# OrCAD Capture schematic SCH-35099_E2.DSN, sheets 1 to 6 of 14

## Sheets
1 07 DMIC: size C; title: X-MIMXRT685-EVK; rev: E2; company: NXP Semiconductors; note: SCH-35099 PDF: SPF-35099; note: 6501 William Cannon Drive West; note: Austin, TX 78735-8598
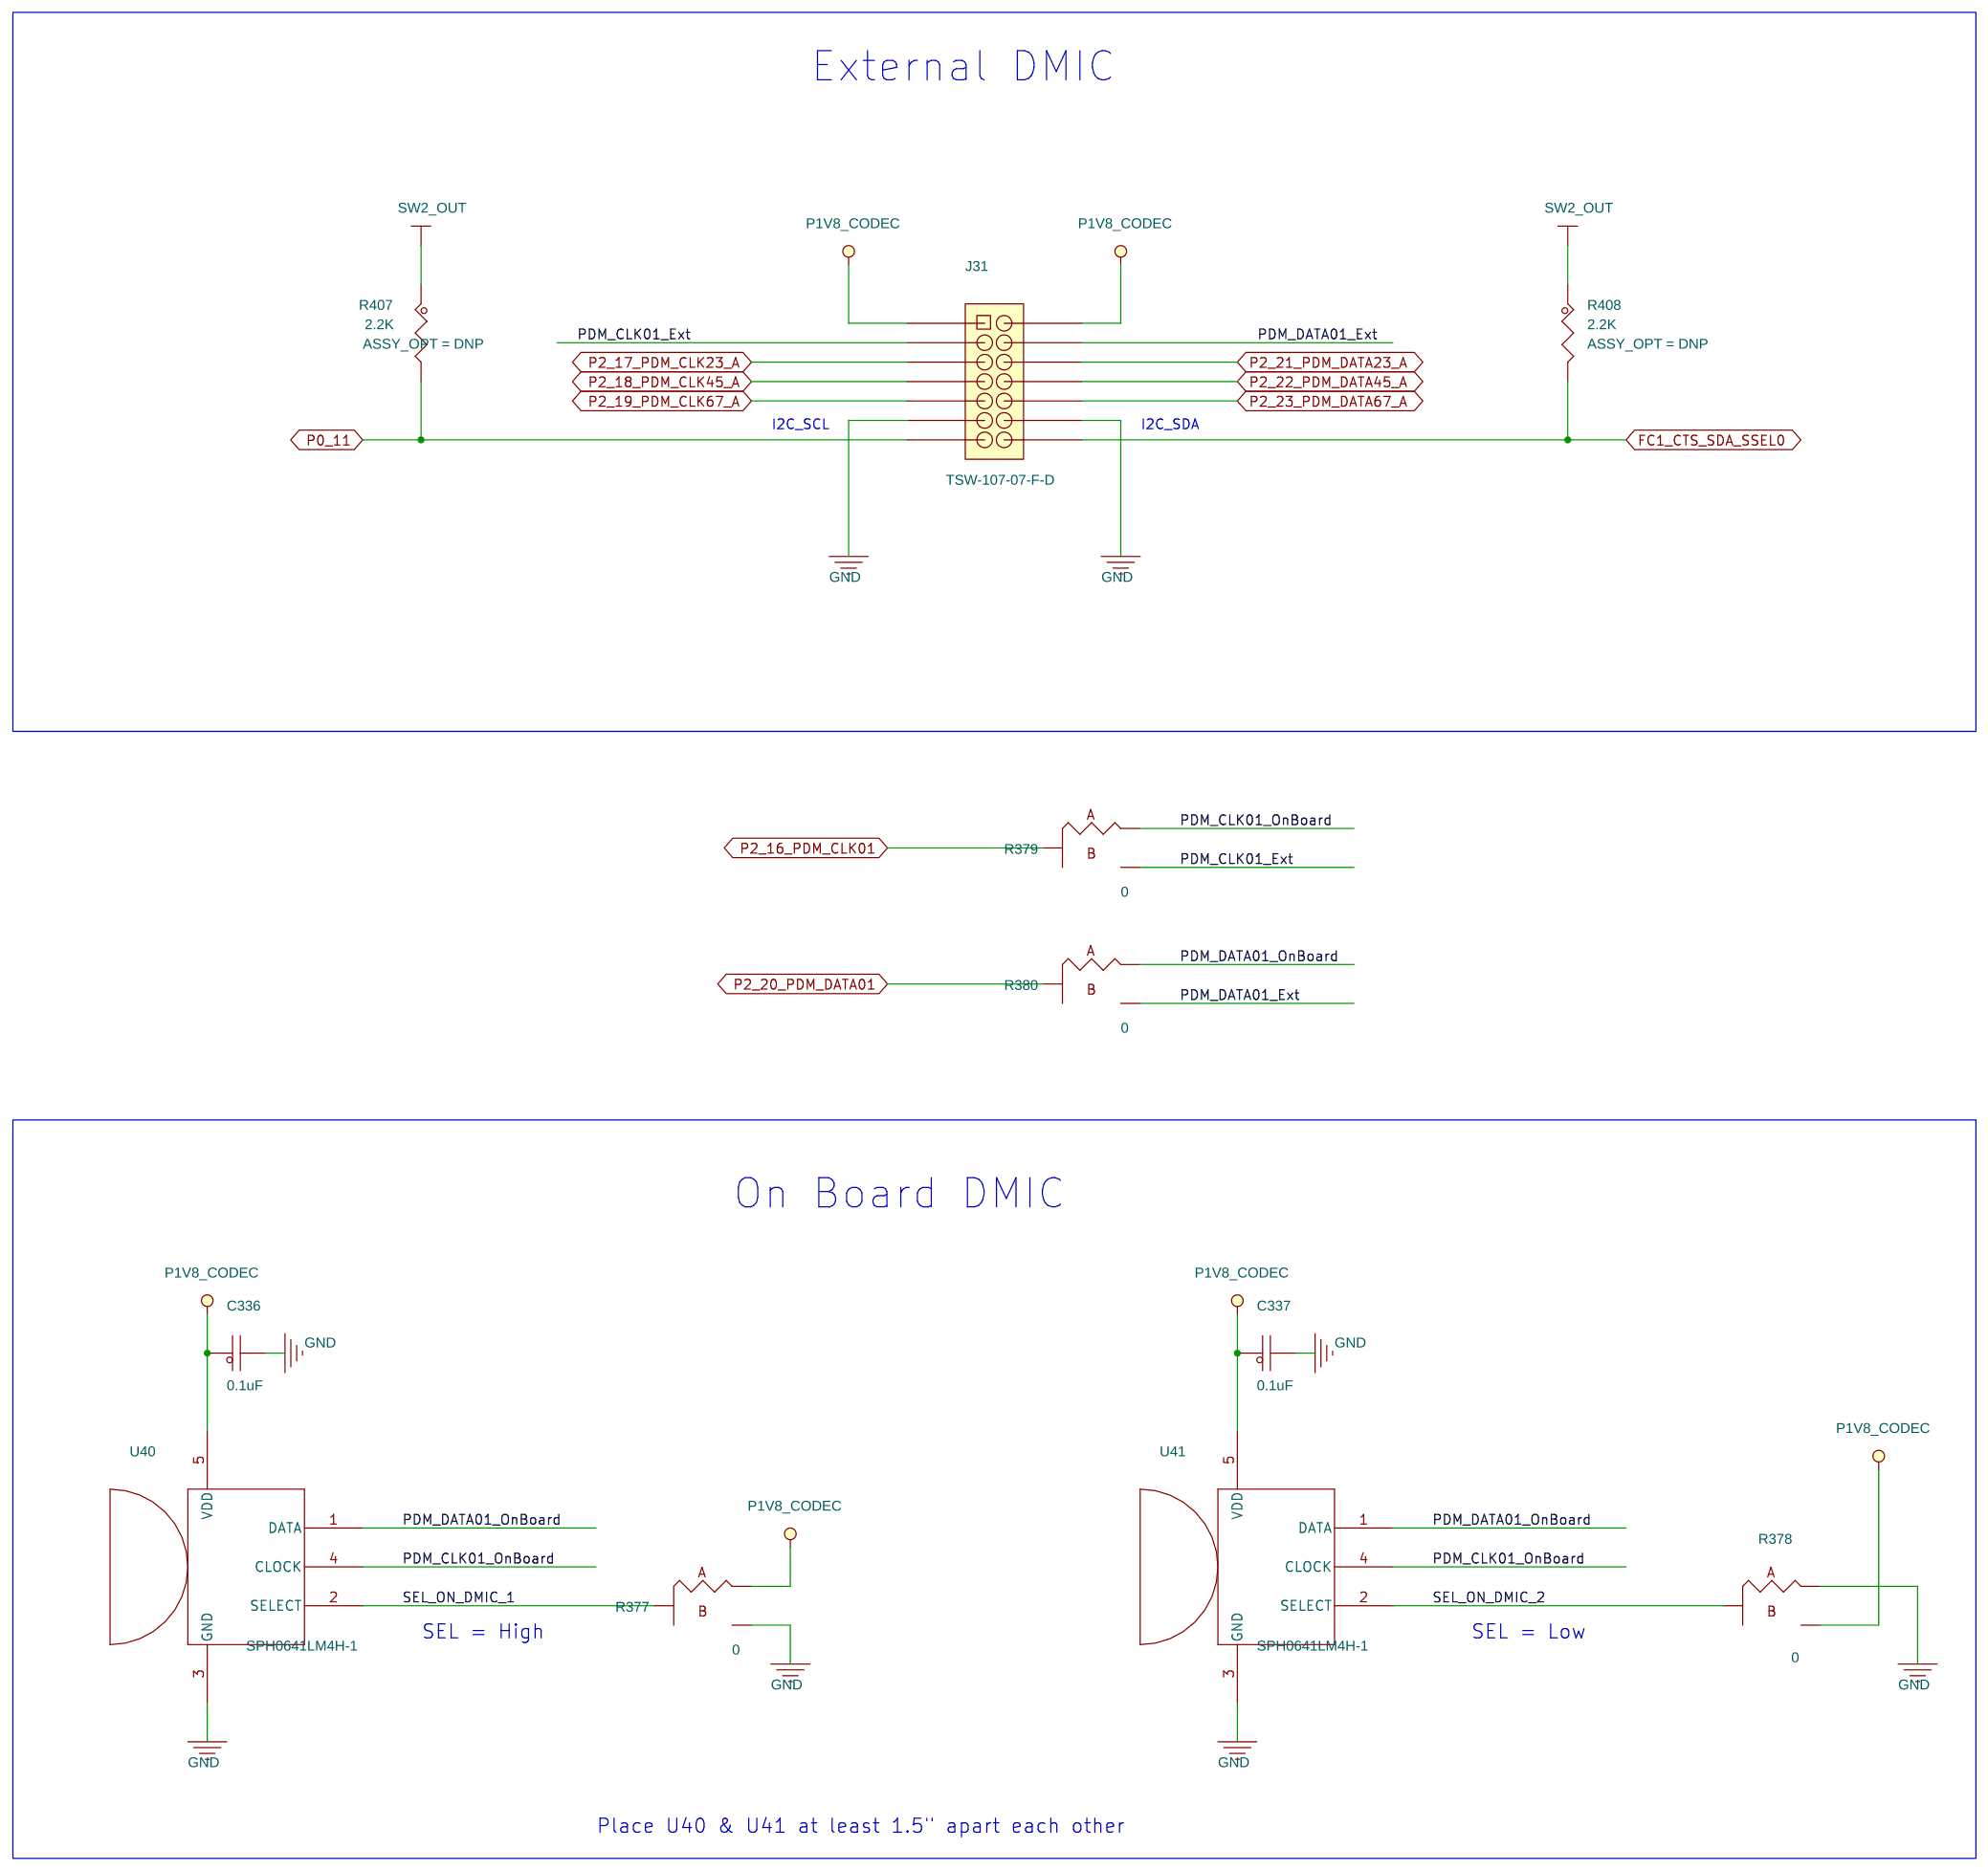
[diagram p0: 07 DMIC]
2 02 USB Supply Interface: size C
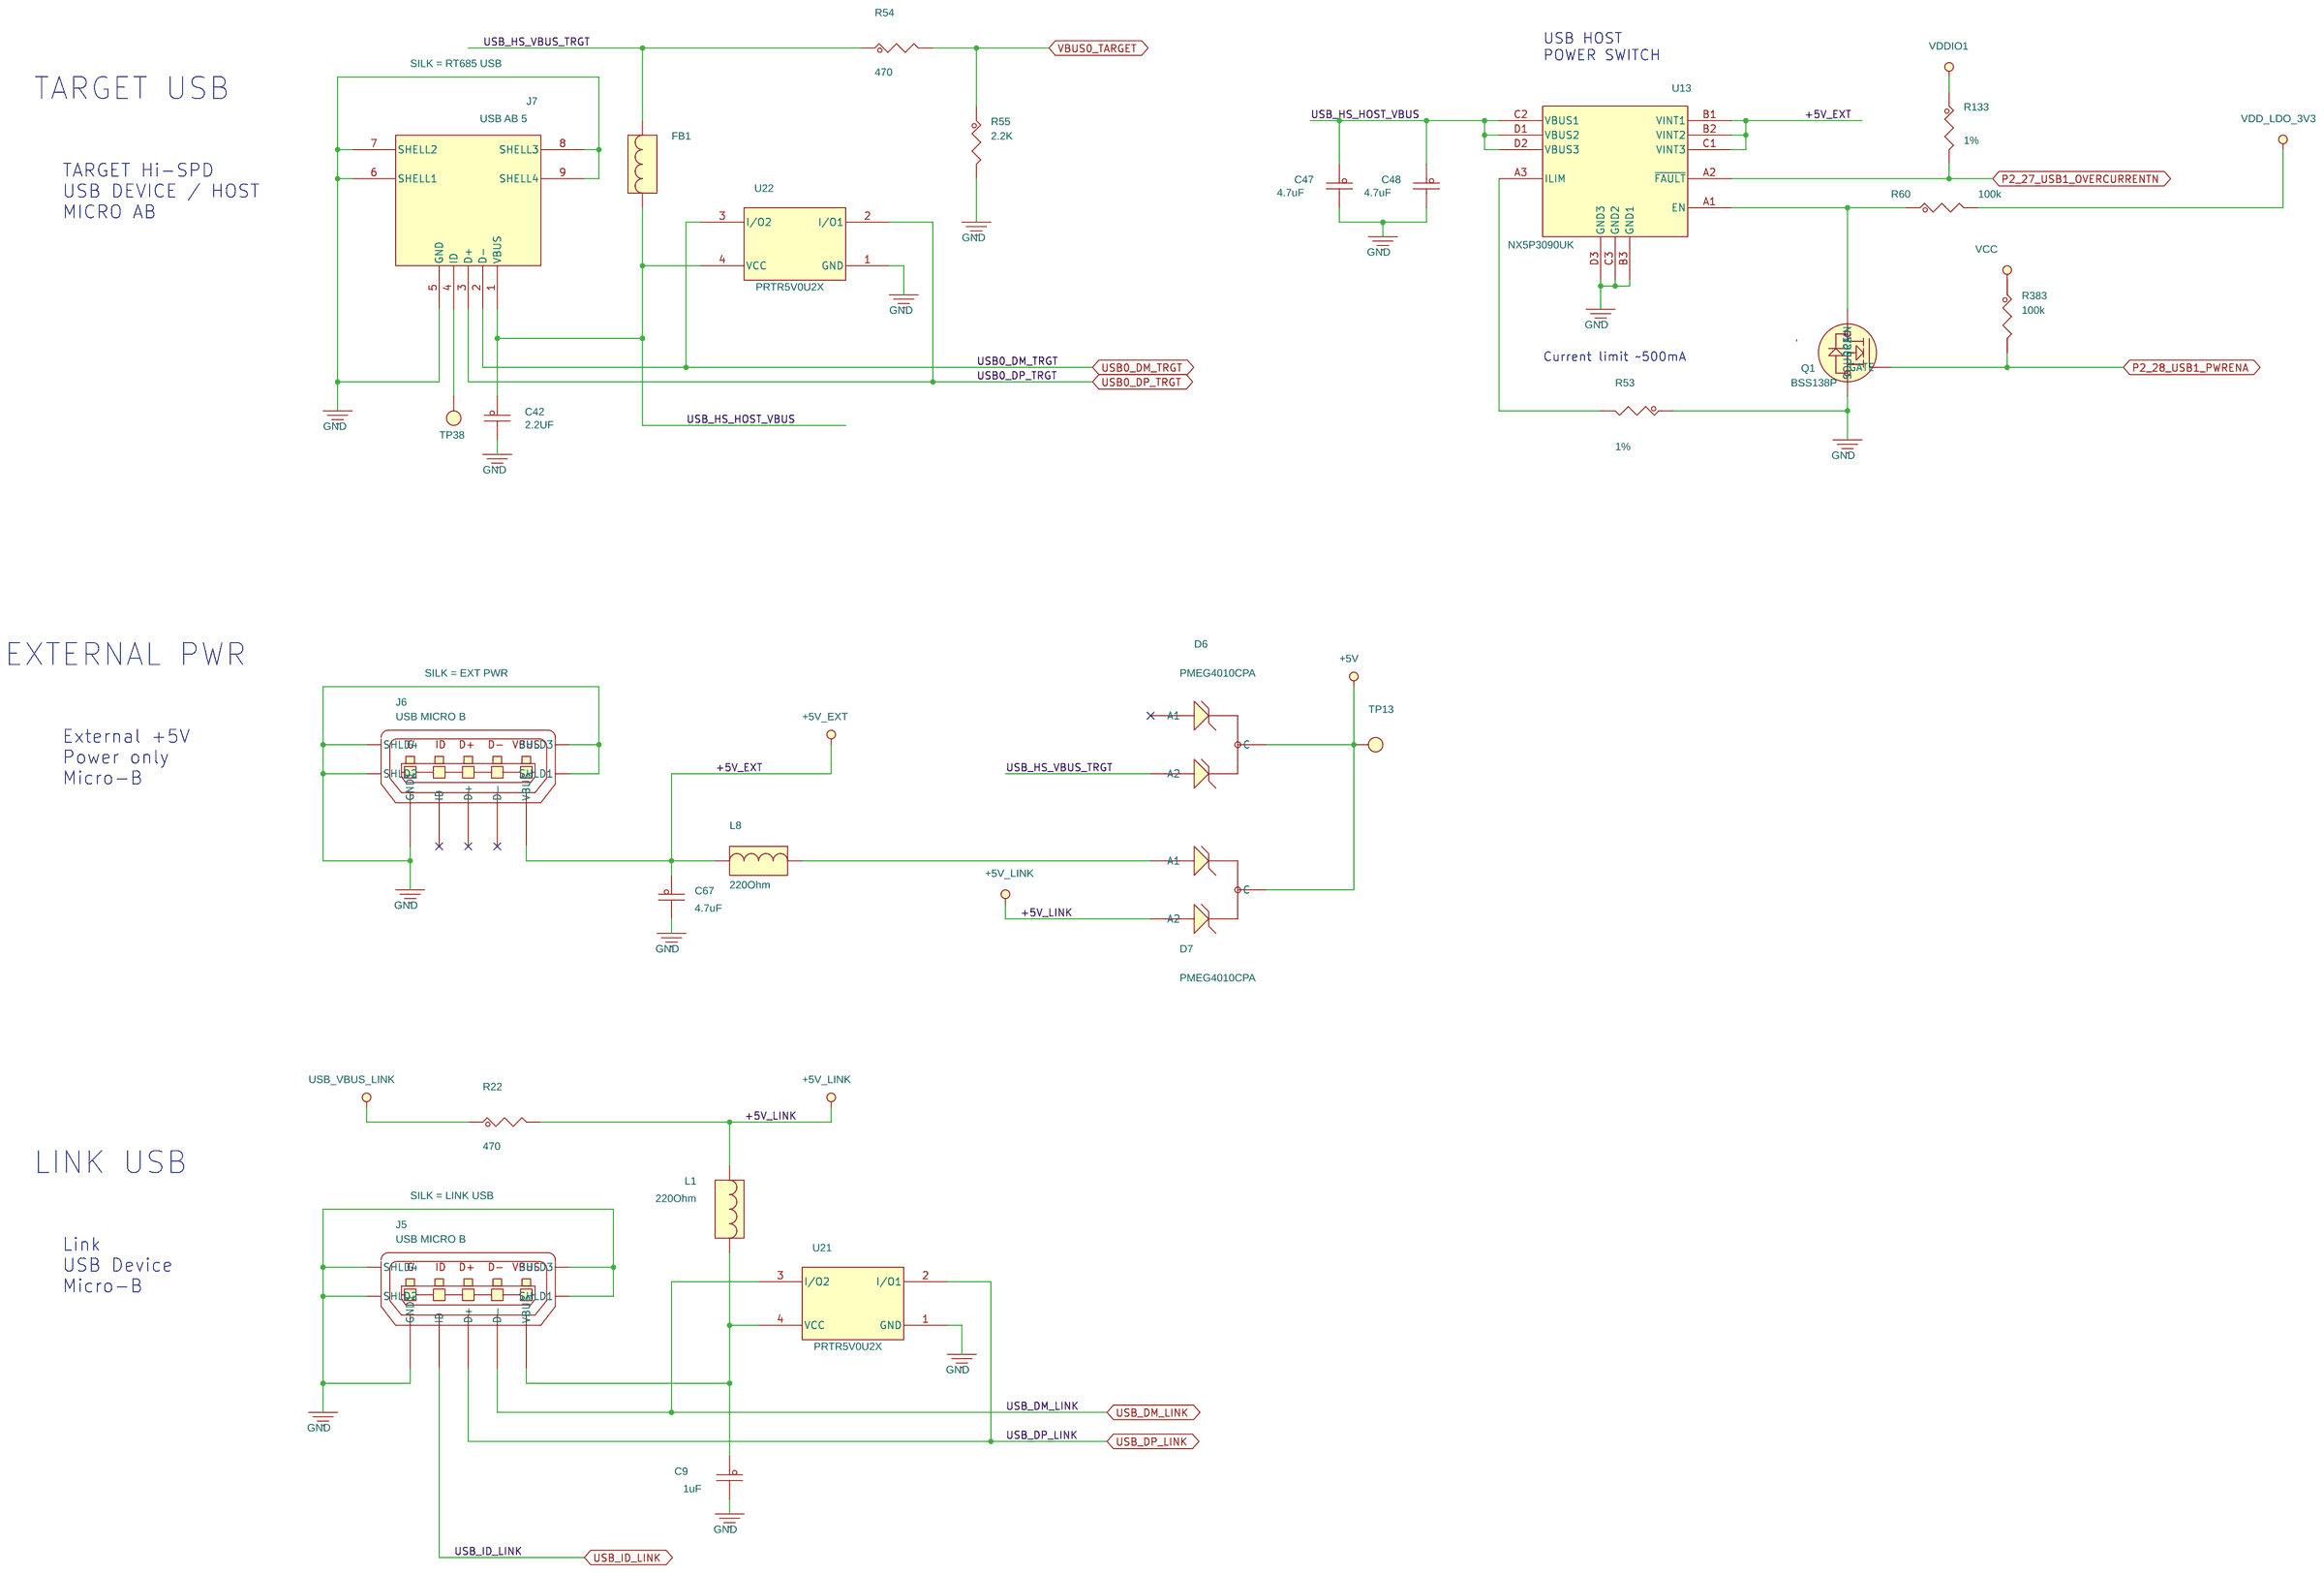
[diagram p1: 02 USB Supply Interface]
3 11 SD & M2 mini card: size C
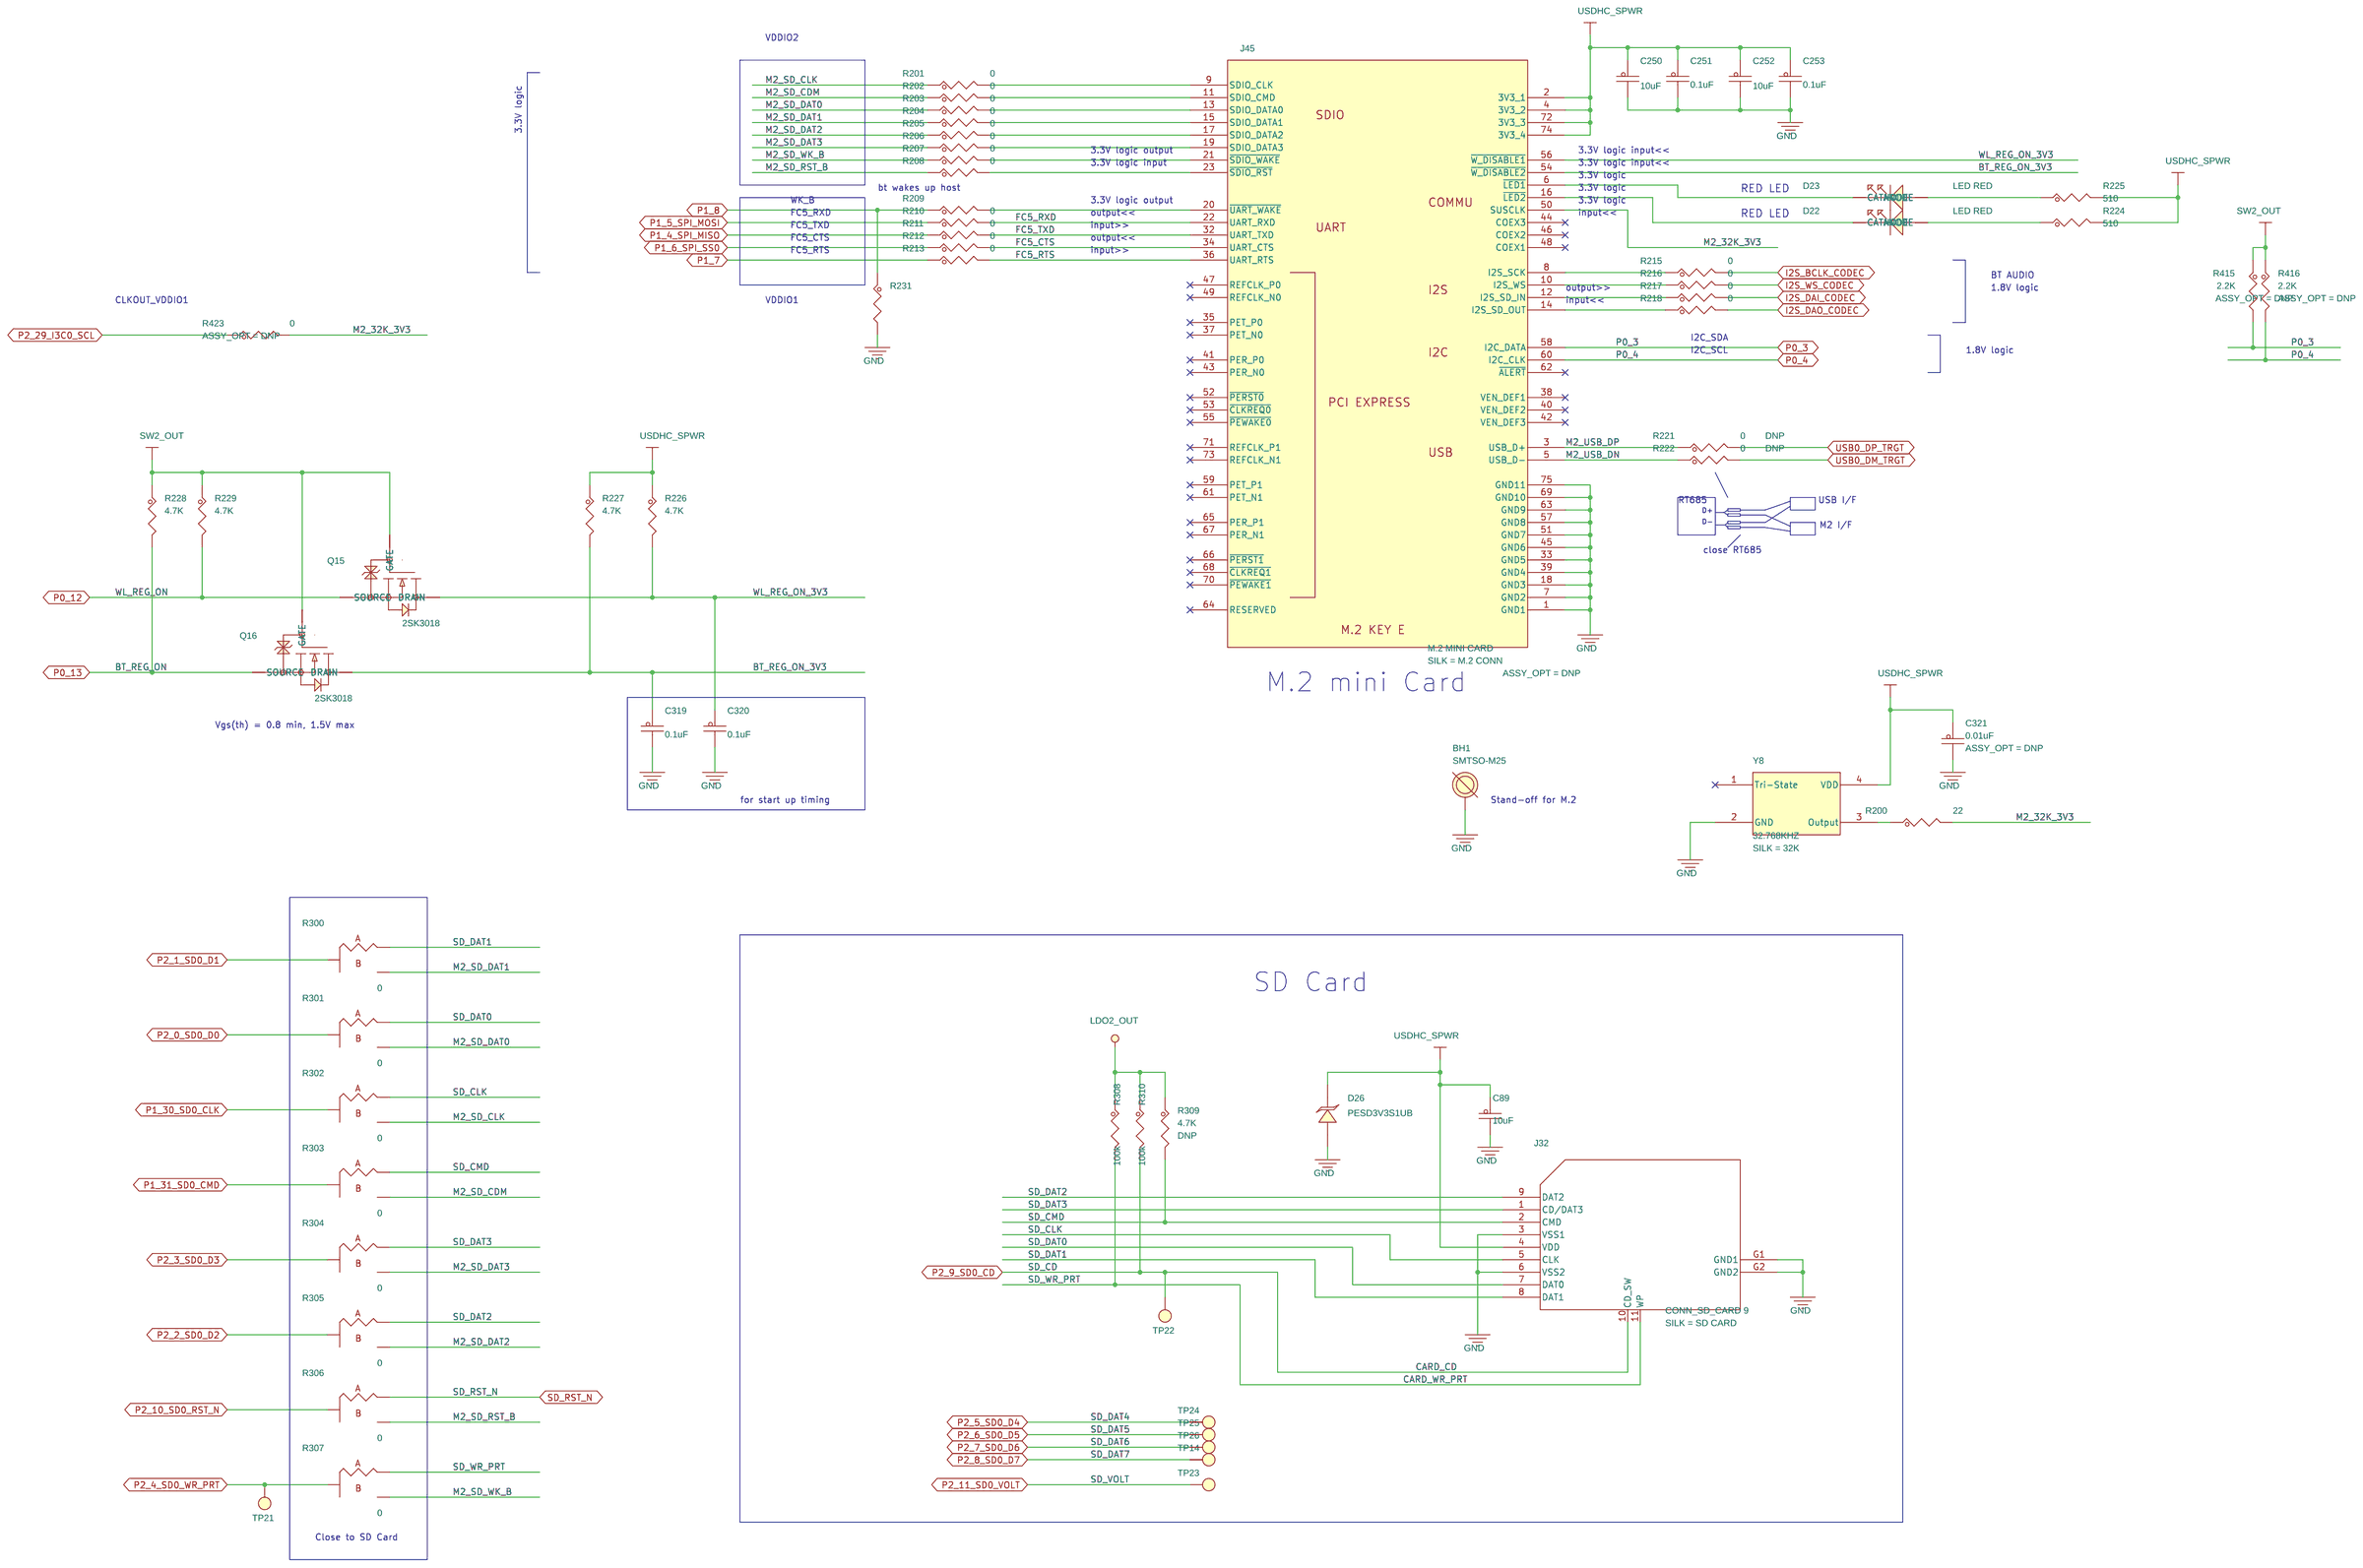
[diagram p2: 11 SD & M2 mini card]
4 12 System Reset: size C
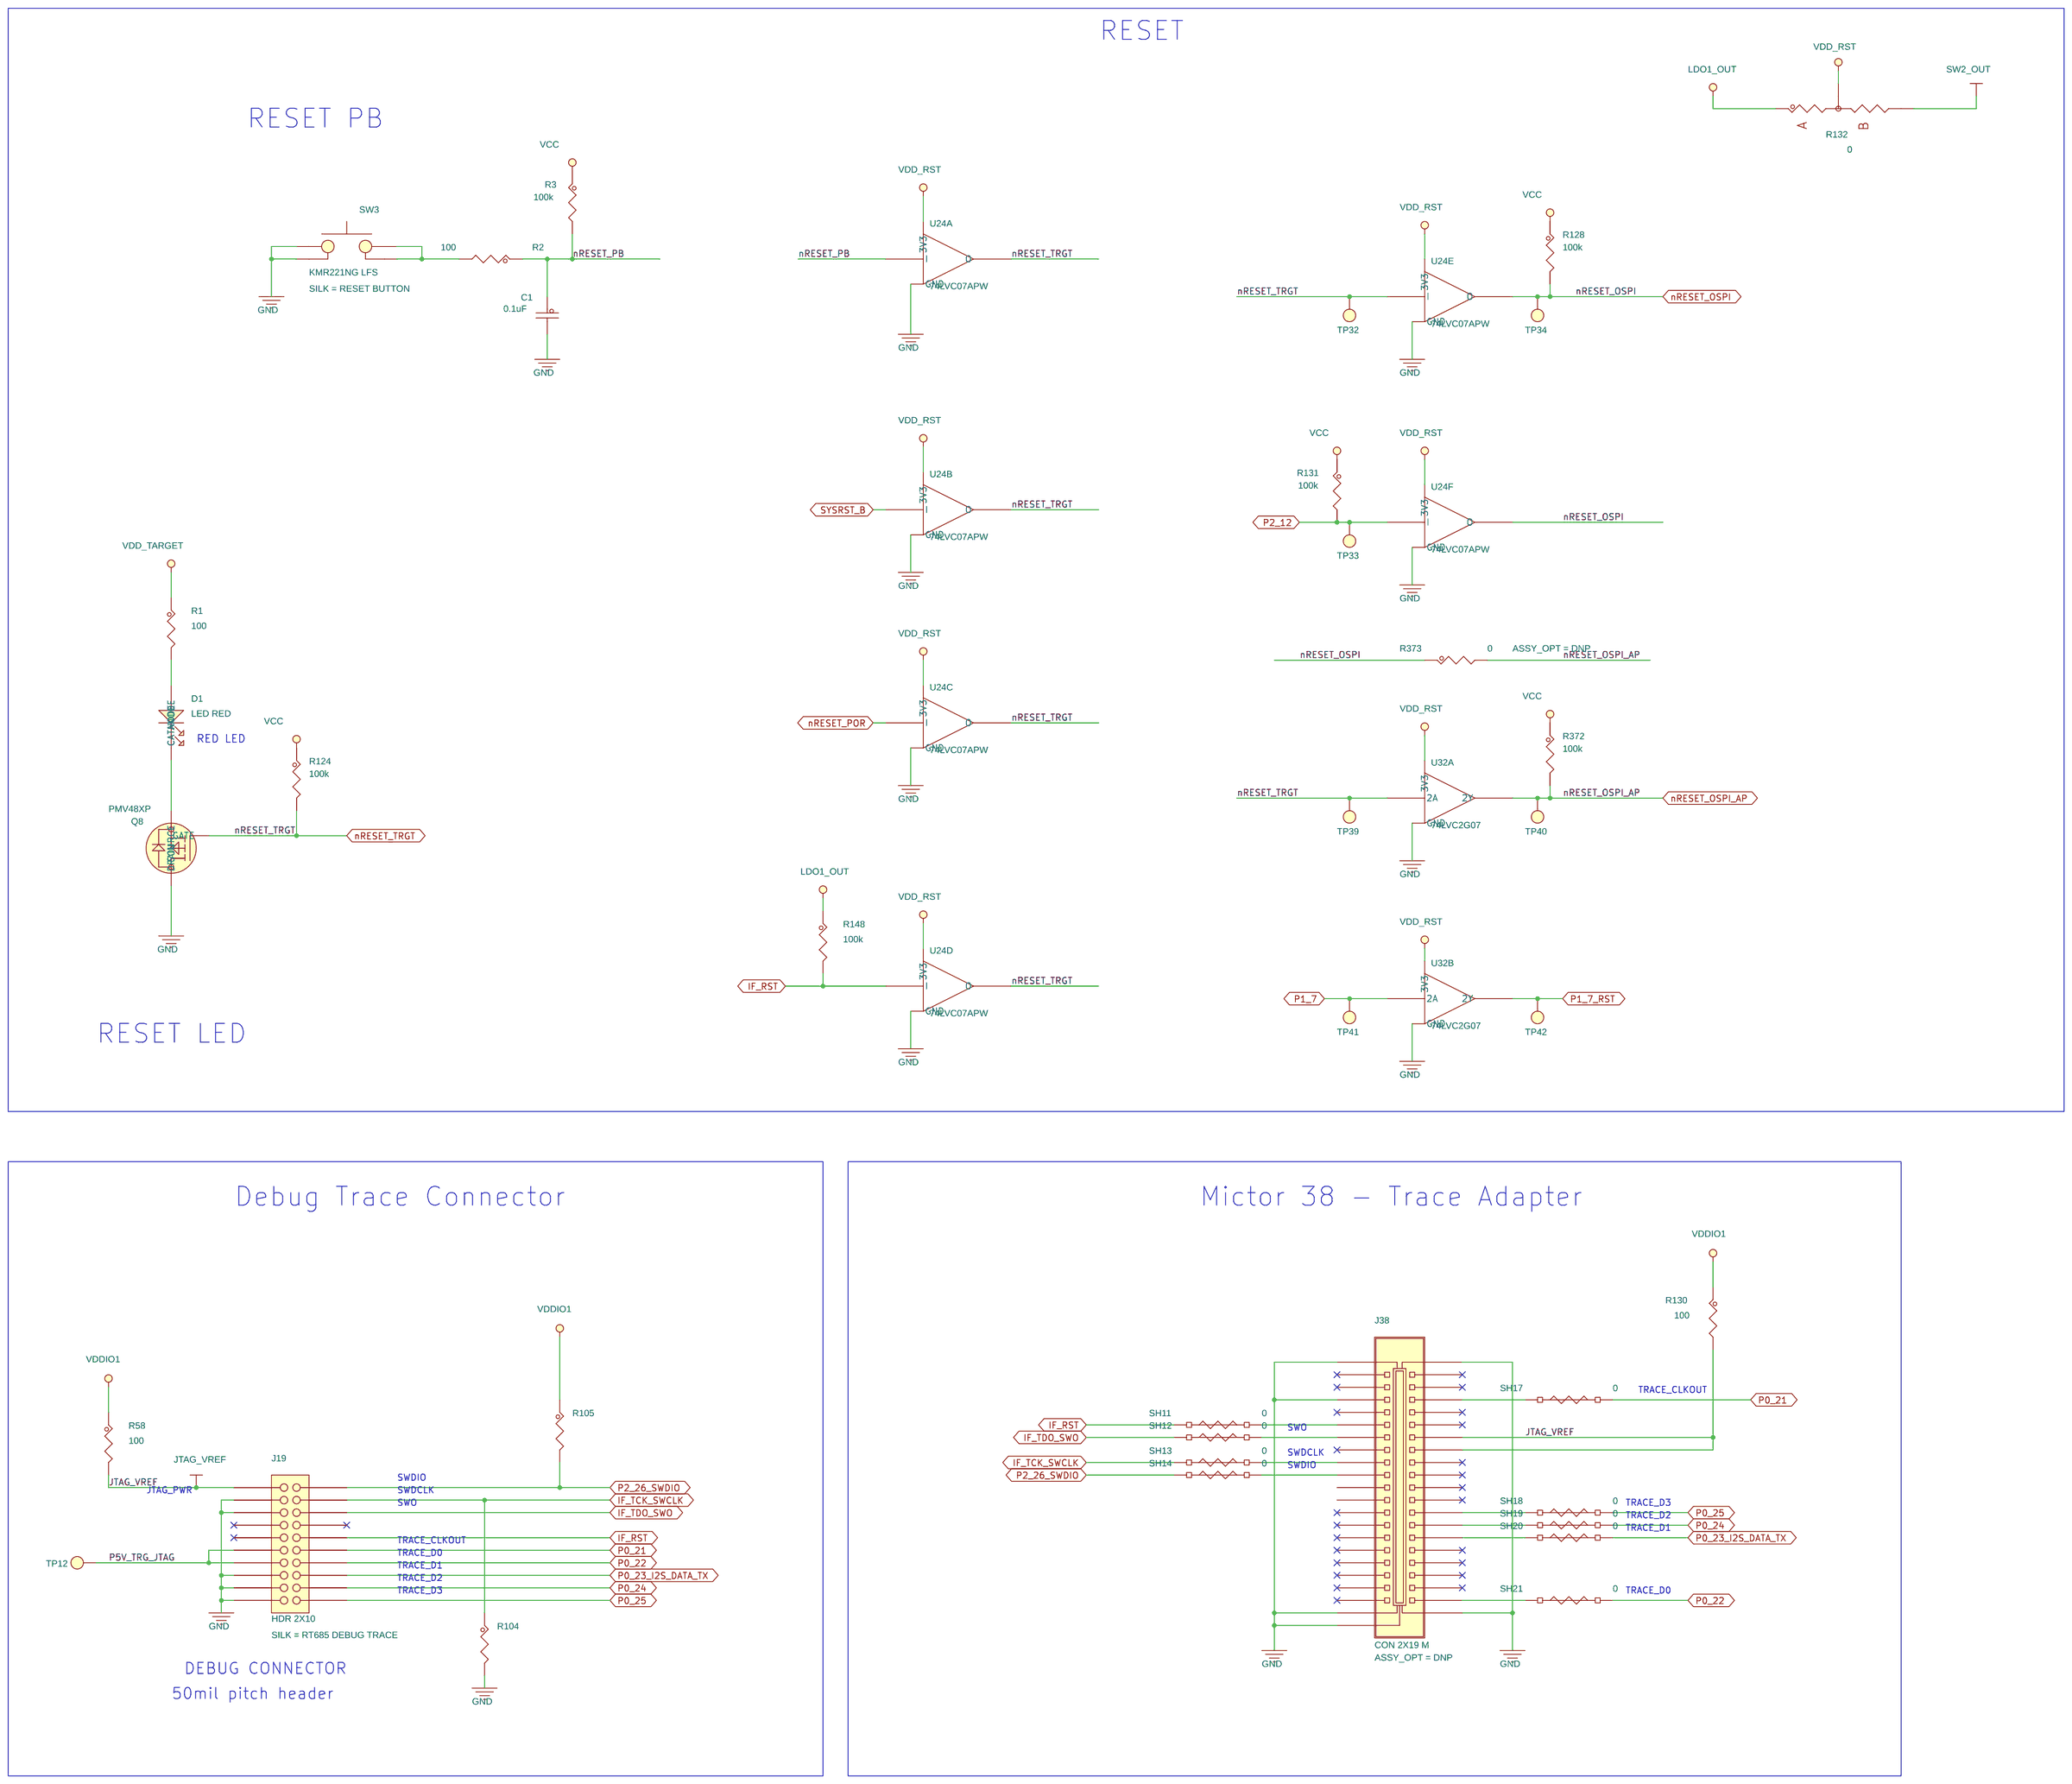
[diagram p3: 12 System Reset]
5 08 Audio Amp: size C
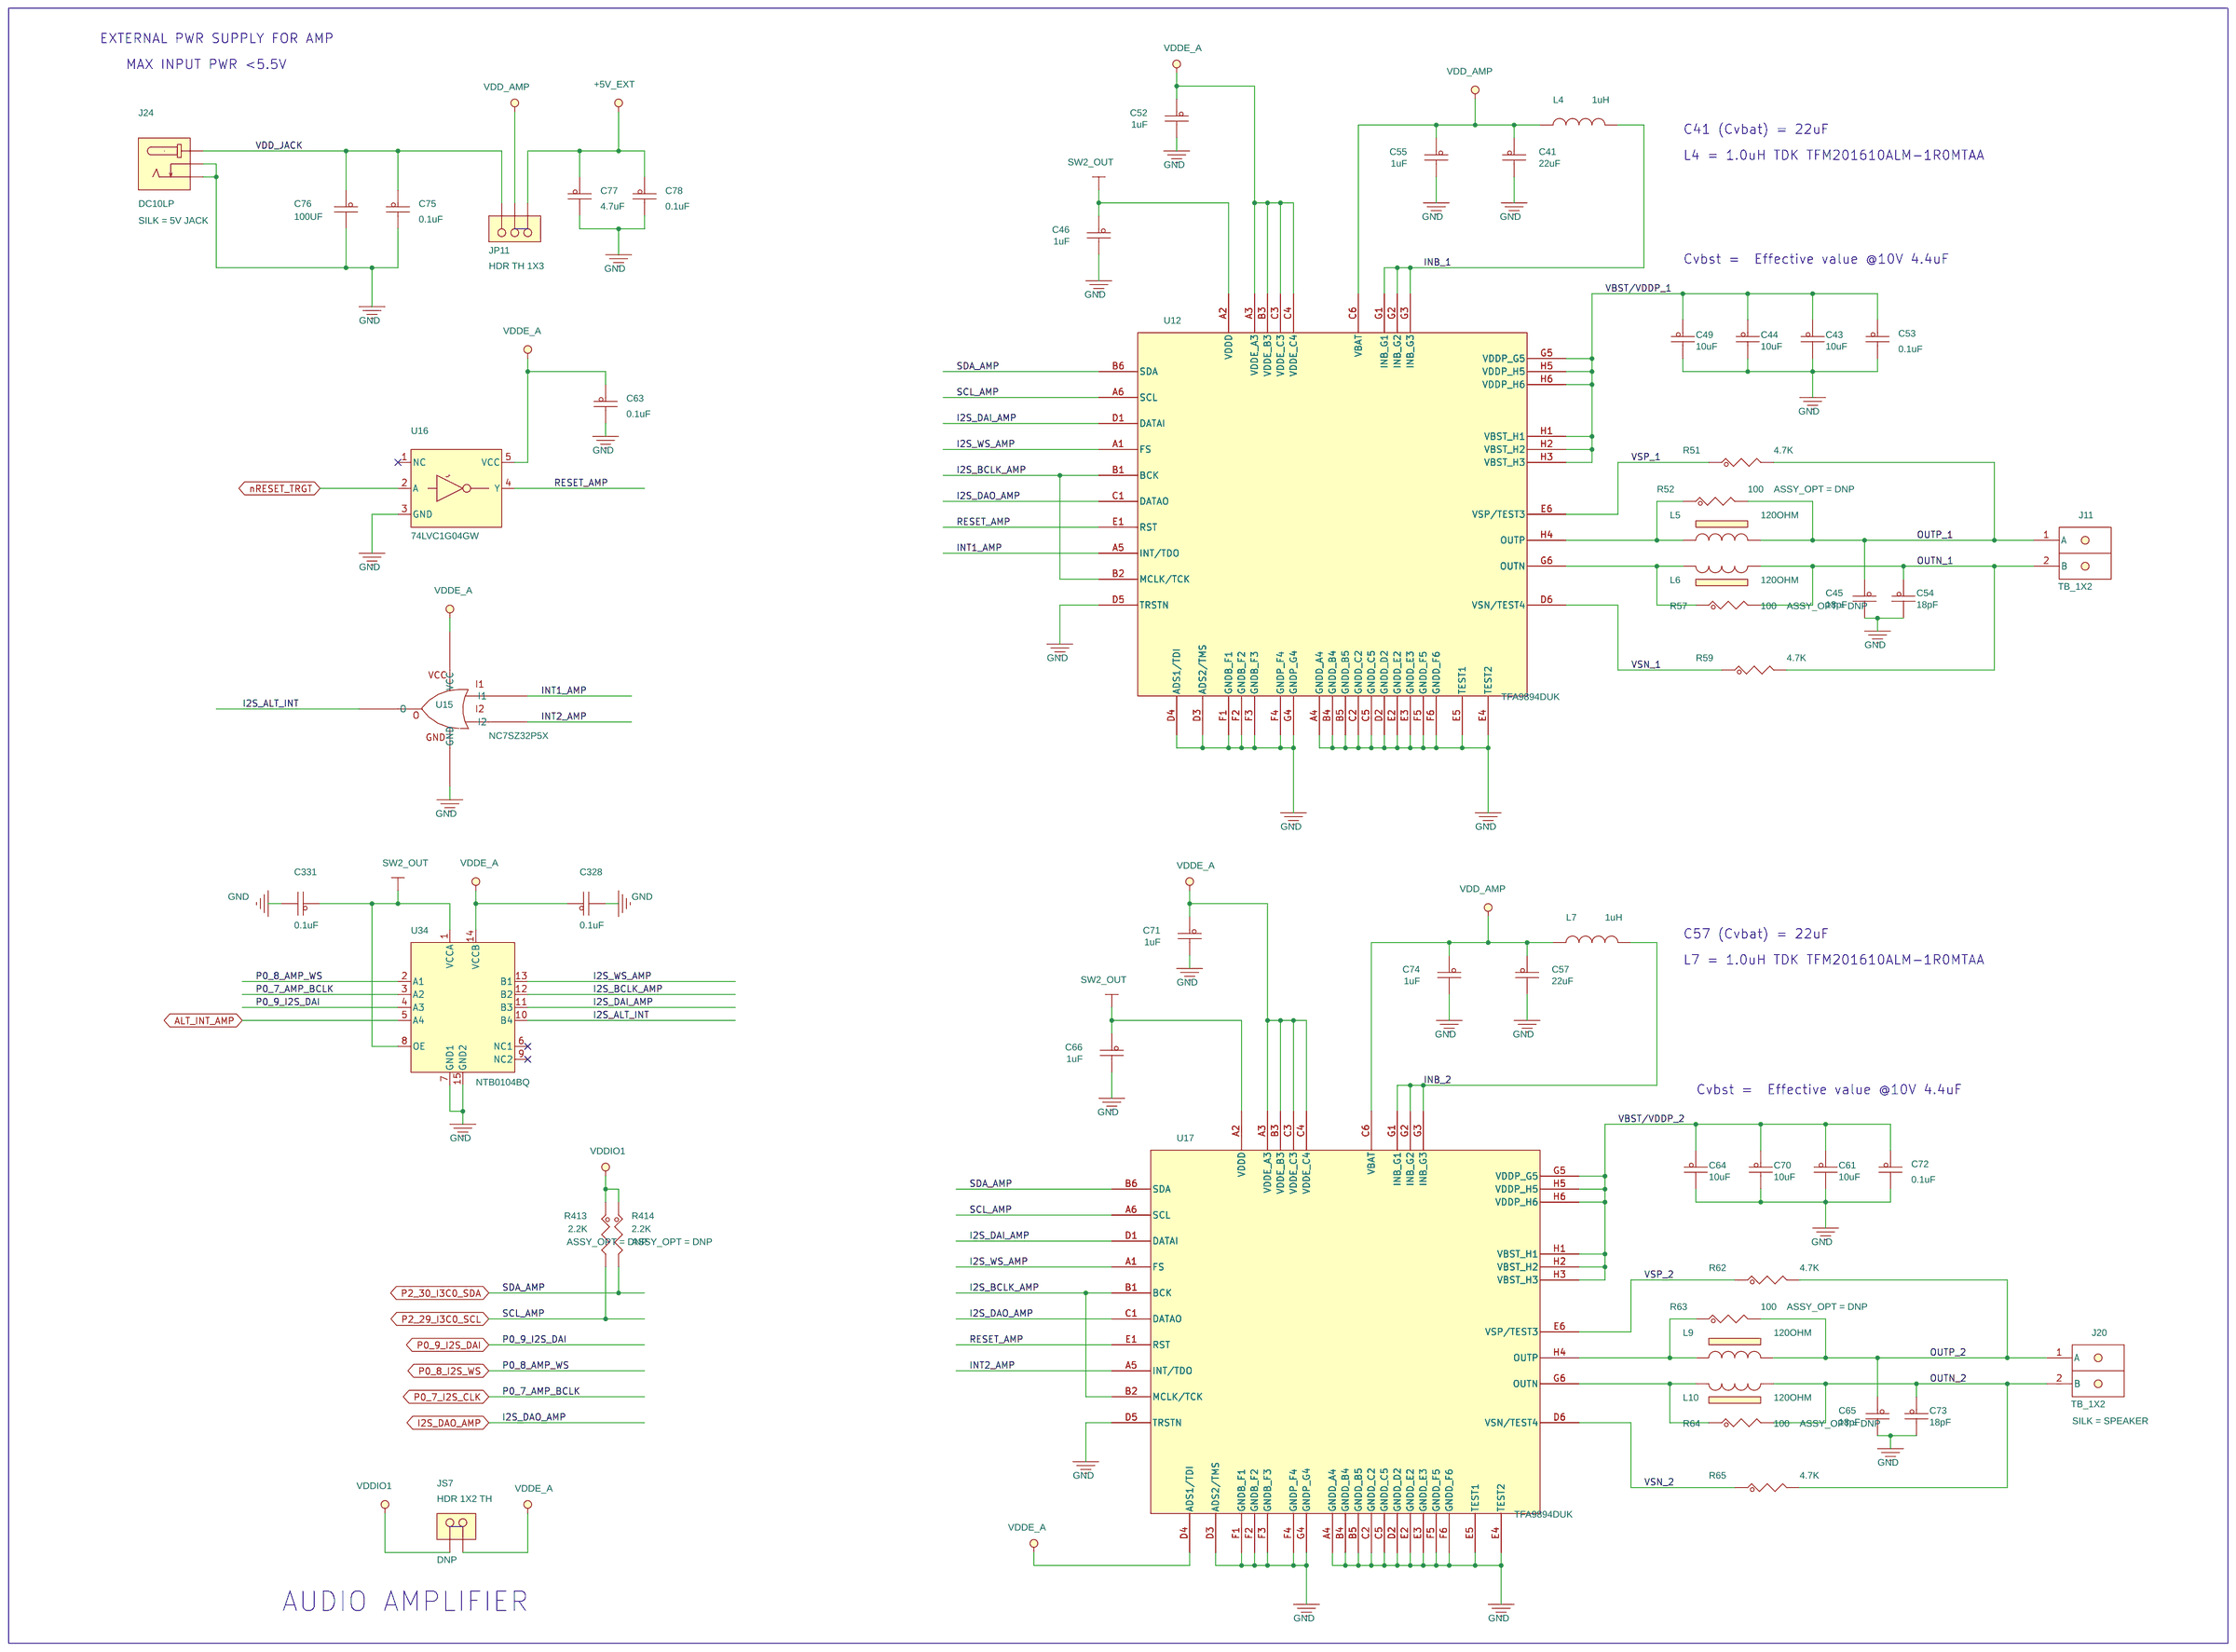
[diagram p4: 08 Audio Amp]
6 01 Title and Rev History
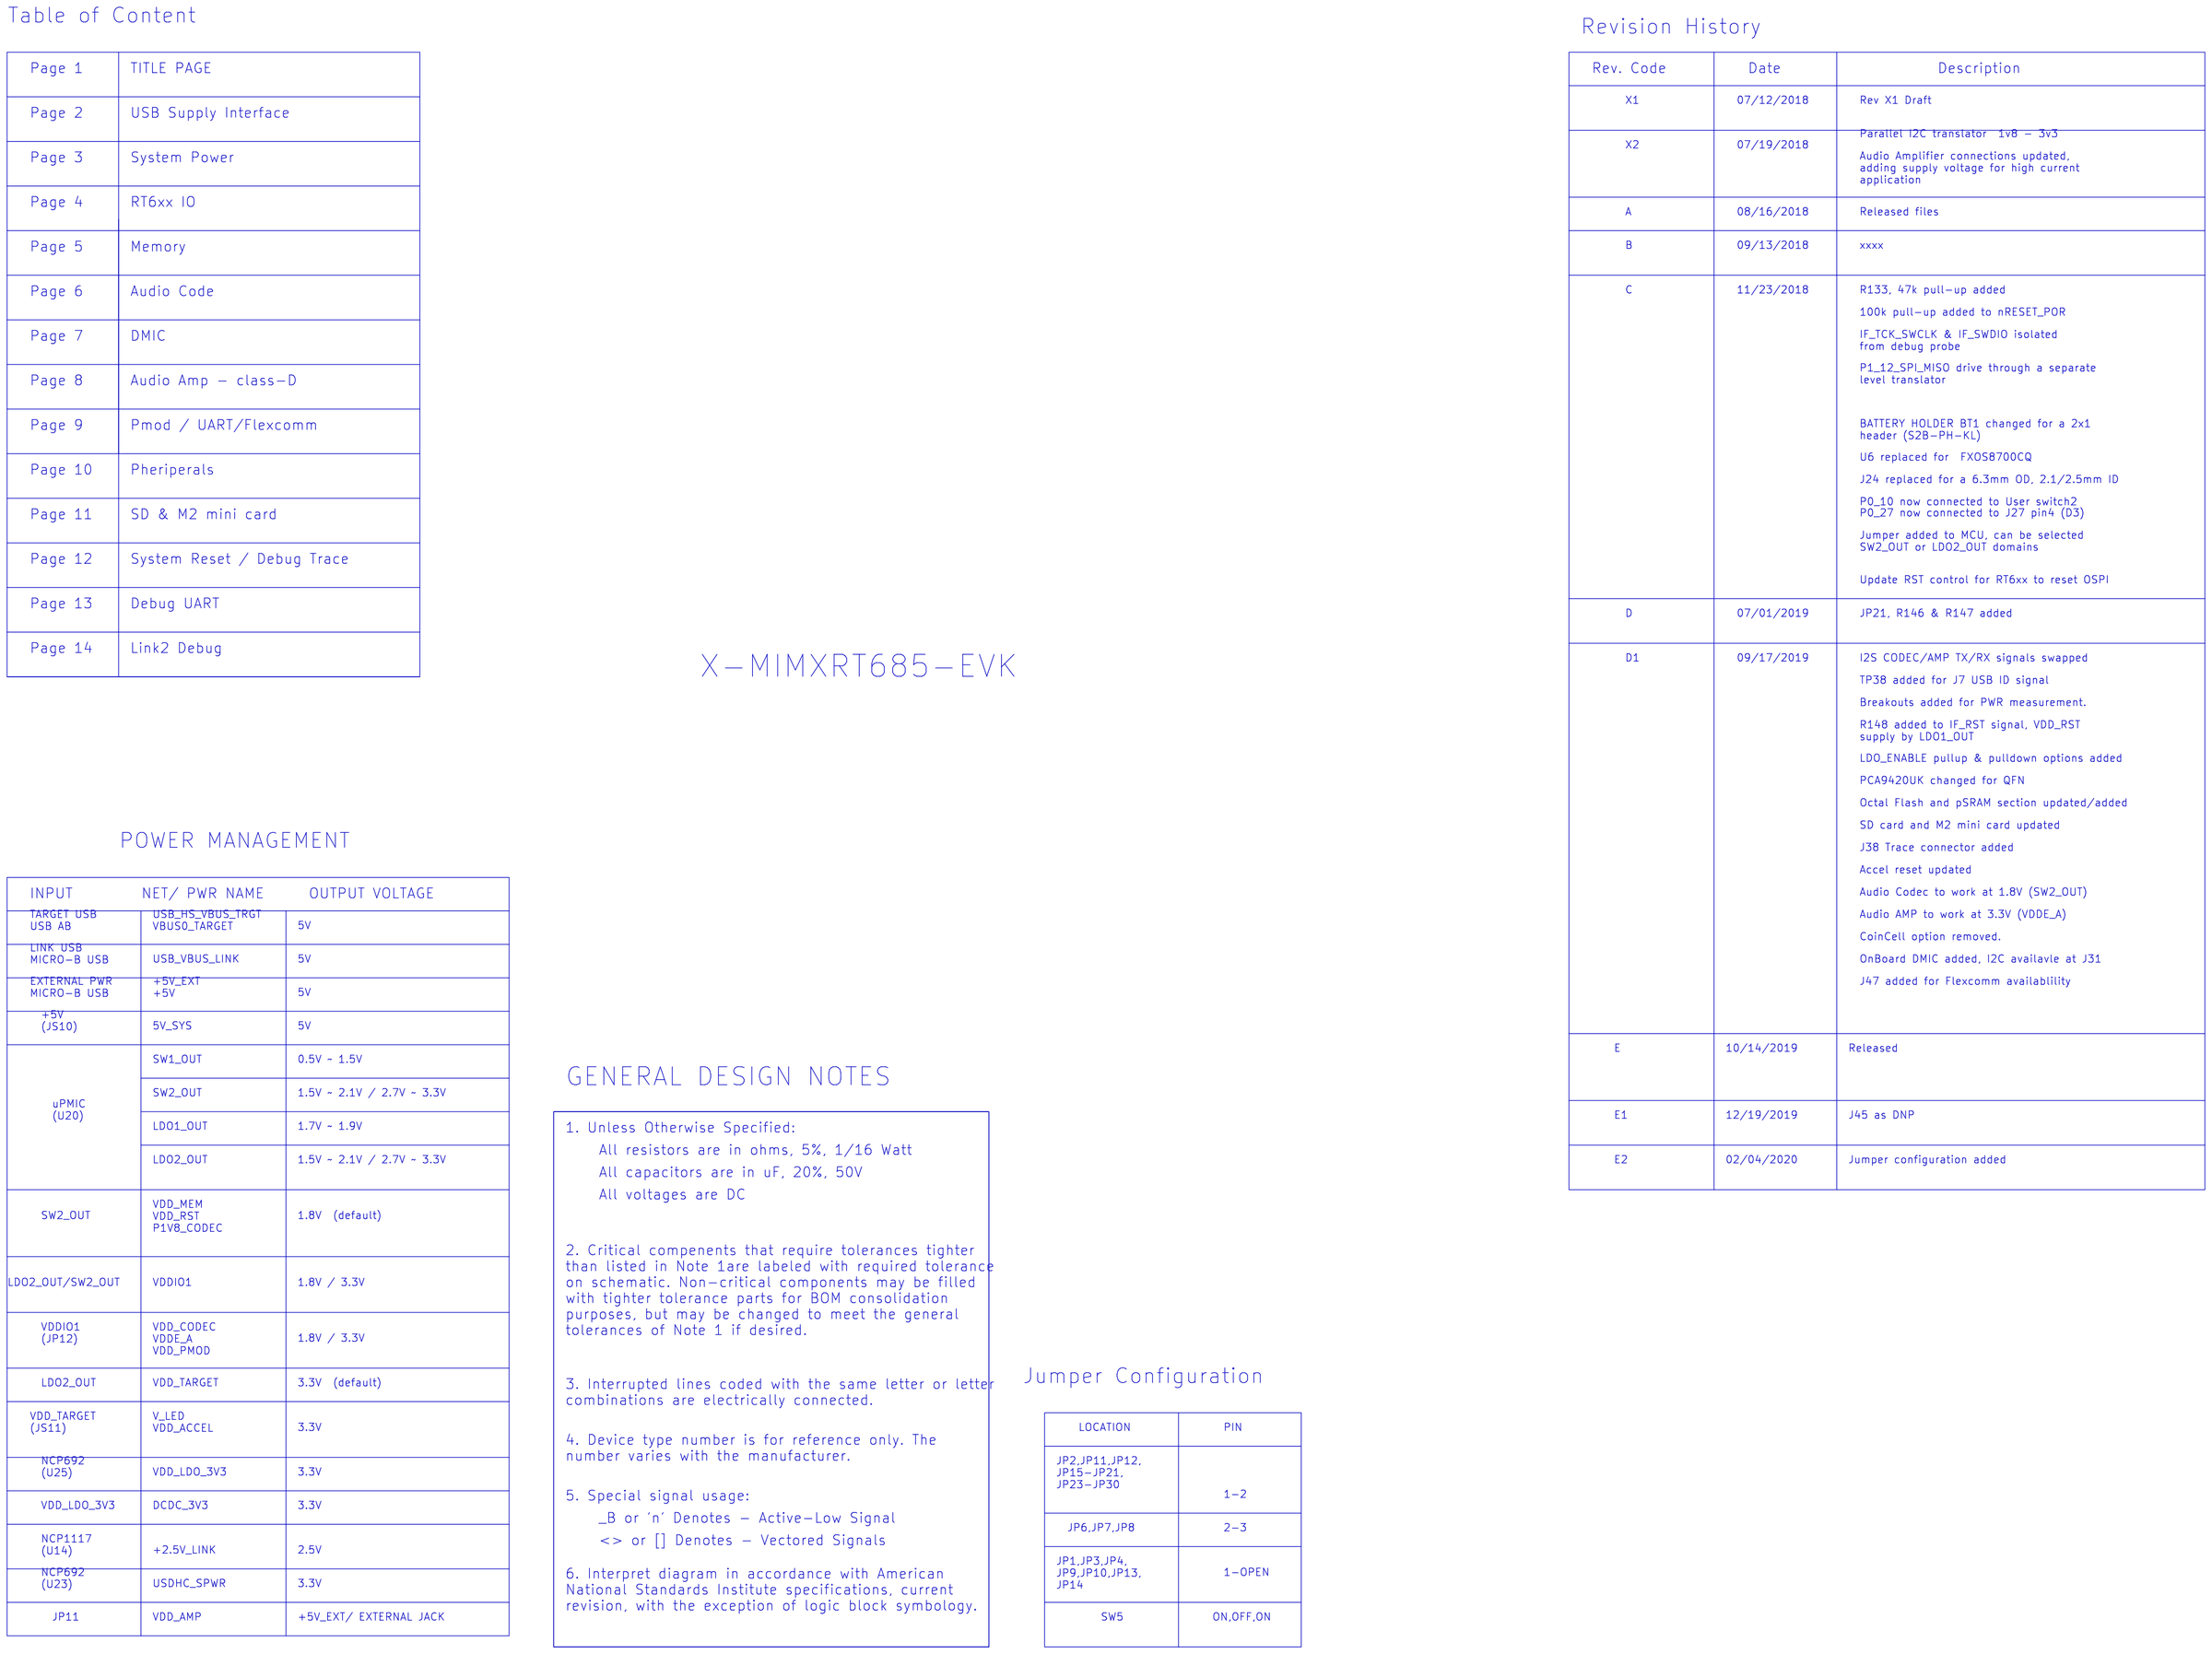
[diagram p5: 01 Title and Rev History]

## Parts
sheet 02 USB Supply Interface
C9  1uF  [cc0402_tol0p15_ov]
C42  2.2UF  [CC0402_25]
C47  4.7uF  [CC0603_OV]
C48  4.7uF  [CC0603_OV]
C67  4.7uF  [CC0603_OV]
D6  PMEG4010CPA  [SOT1061]
D7  PMEG4010CPA  [SOT1061]
FB1  330 OHM  [ind_1608]
J5  USB MICRO B  [usb_micro_b_0p65_sm_ra]
J6  USB MICRO B  [usb_micro_b_0p65_sm_ra]
J7  USB AB 5  [con9_microAB_usb_shell_th]
L1  220Ohm  [IND_0603]
L8  220Ohm  [IND_0603]
Q1  BSS138P  [sot23_a]
R22  470  [RC0402_25]
R53  47K  [RC0402_25]
R54  470  [RC0402_25]
R55  2.2K  [RC0402_25]
R60  100k  [RC0402_25]
R133  47K  [RC0402_25]
R383  100k  [RC0402_25]
TP13  TPAD_050  [TPAD_050]
TP38  TPAD_050  [TPAD_050]
U13  NX5P3090UK  [wlcsp12_0p4_1p38x1p68mm_smdp]
U21  PRTR5V0U2X  [SOT143B]
U22  PRTR5V0U2X  [SOT143B]
sheet 07 DMIC
C336  0.1uF  [CC0402_25]
C337  0.1uF  [CC0402_25]
J31  TSW-107-07-F-D  [JUMP2X7-6040]
R377  0  [R603-X2]
R378  0  [R603-X2]
R379  0  [R603-X2]
R380  0  [R603-X2]
R407  2.2K  [RC0402_25]
R408  2.2K  [RC0402_25]
U40  SPH0641LM4H-1  [mic5_3p6x2p75mm]
U41  SPH0641LM4H-1  [mic5_3p6x2p75mm]
sheet 08 Audio Amp
C41  22uF  [CC0603_OV]
C43  10uF  [CC0603_OV]
C44  10uF  [CC0603_OV]
C45  18pF  [CC0402_25]
C46  1uF  [cc0402_tol0p15_ov]
C49  10uF  [CC0603_OV]
C52  1uF  [cc0402_tol0p15_ov]
C53  0.1uF  [CC0402_25]
C54  18pF  [CC0402_25]
C55  1uF  [cc0402_tol0p15_ov]
C57  22uF  [CC0603_OV]
C61  10uF  [CC0603_OV]
C63  0.1uF  [CC0402_25]
C64  10uF  [CC0603_OV]
C65  18pF  [CC0402_25]
C66  1uF  [cc0402_tol0p15_ov]
C70  10uF  [CC0603_OV]
C71  1uF  [cc0402_tol0p15_ov]
C72  0.1uF  [CC0402_25]
C73  18pF  [CC0402_25]
C74  1uF  [cc0402_tol0p15_ov]
C75  0.1uF  [CC0402_25]
C76  100UF  [CC1210]
C77  4.7uF  [CC0603_OV]
C78  0.1uF  [CC0402_25]
C328  0.1uF  [CC0402_25]
C331  0.1uF  [CC0402_25]
J11  TB_1X2  [con2_tb_5mm_10x7p5mm_th]
J20  TB_1X2  [con2_tb_5mm_10x7p5mm_th]
J24  DC10LP  [con3_skt_dc_power]
JP11  HDR TH 1X3  [HDR103]
JS7  HDR 1X2 TH  [SH_HDR102_BOTTOM]
L4  1uH  [ind_2016a]
L5  120OHM  [IND_0402]
L6  120OHM  [IND_0402]
L7  1uH  [ind_2016a]
L9  120OHM  [IND_0402]
L10  120OHM  [IND_0402]
R51  4.7K  [RC0402_25]
R52  100  [RC0402_25]
R57  100  [RC0402_25]
R59  4.7K  [RC0402_25]
R62  4.7K  [RC0402_25]
R63  100  [RC0402_25]
R64  100  [RC0402_25]
R65  4.7K  [RC0402_25]
R413  2.2K  [RC0402_25]
R414  2.2K  [RC0402_25]
U12  TFA9894DUK  [wlcsp48_0p4_2p51x3p55]
U15  NC7SZ32P5X  [SC70-5]
U16  74LVC1G04GW  [sc70-5]
U17  TFA9894DUK  [wlcsp48_0p4_2p51x3p55]
U34  NTB0104BQ  [dhvqfn14_3x2p5mm]
sheet 11 SD & M2 mini card
BH1  SMTSO-M25  [mh244-166t]
C89  10uF  [cc0603_0805_nsp]
C250  10uF  [CC0603_OV]
C251  0.1uF  [CC0201]
C252  10uF  [CC0603_OV]
C253  0.1uF  [CC0201]
C319  0.1uF  [CC0201]
C320  0.1uF  [CC0201]
C321  0.01uF  [CC0201]
D22  LED RED  [LED_0603]
D23  LED RED  [LED_0603]
D26  PESD3V3S1UB  [sod523]
J32  CONN_SD_CARD 9  [con_sdcard_28p9x29_sm_ra]
J45  M.2 MINI CARD  [con_67_0p5_22x7p75_ra]
Q15  2SK3018  [SOT323_3]
Q16  2SK3018  [SOT323_3]
R200  22  [RC0402_25]
R201  0  [RC0402_25]
R202  0  [RC0402_25]
R203  0  [RC0402_25]
R204  0  [RC0402_25]
R205  0  [RC0402_25]
R206  0  [RC0402_25]
R207  0  [RC0402_25]
R208  0  [RC0402_25]
R209  10K  [0402_CC]
R210  0  [RC0402_25]
R211  0  [RC0402_25]
R212  0  [RC0402_25]
R213  0  [RC0402_25]
R215  0  [RC0402_25]
R216  0  [RC0402_25]
R217  0  [RC0402_25]
R218  0  [RC0402_25]
R221  0  [RC0402_25]
R222  0  [RC0402_25]
R224  510  [RC0402_25]
R225  510  [RC0402_25]
R226  4.7K  [RC0402_25]
R227  4.7K  [RC0402_25]
R228  4.7K  [RC0402_25]
R229  4.7K  [RC0402_25]
R231  10K  [0402_CC]
R300  0  [R603-X2]
R301  0  [R603-X2]
R302  0  [R603-X2]
R303  0  [R603-X2]
R304  0  [R603-X2]
R305  0  [R603-X2]
R306  0  [R603-X2]
R307  0  [R603-X2]
R308  100k  [RC0402_25]
R309  4.7K  [RC0402_25]
R310  100k  [RC0402_25]
R415  2.2K  [RC0402_25]
R416  2.2K  [RC0402_25]
R423  0  [RC0402_25]
TP14  TPAD_050  [TPAD_050]
TP21  TPAD_050  [TPAD_050]
TP22  TPAD_050  [TPAD_050]
TP23  TPAD_050  [TPAD_050]
TP24  TPAD_050  [TPAD_050]
TP25  TPAD_050  [TPAD_050]
TP26  TPAD_050  [TPAD_050]
Y8  32.768KHZ  [xtal4_3p3x2p6_sm_fl]
sheet 12 System Reset
C1  0.1uF  [CC0402_25]
D1  LED RED  [LED_0603]
J19  HDR 2X10  [HDR210_FTSH_SM]
J38  CON 2X19 M  [con_mic_38m_25_sm]
Q8  PMV48XP  [sot23_a]
R1  100  [RC0402_25]
R2  100  [RC0402_25]
R3  100k  [RC0402_25]
R58  100  [RC0402_25]
R104  10K  [0402_CC]
R105  10K  [0402_CC]
R124  100k  [RC0402_25]
R128  100k  [RC0402_25]
R130  100  [RC0402_25]
R131  100k  [RC0402_25]
R132  0  [R603-X2]
R148  100k  [RC0402_25]
R372  100k  [RC0402_25]
R373  0  [RC0402_25]
SH11  0  [SH0603]
SH12  0  [SH0603]
SH13  0  [SH0603]
SH14  0  [SH0603]
SH17  0  [SH0603]
SH18  0  [SH0603]
SH19  0  [SH0603]
SH20  0  [SH0603]
SH21  0  [SH0603]
SW3  KMR221NG LFS  [sw4_4p2x2p8_sm]
TP12  TPAD_050  [TPAD_050]
TP32  TPAD_050  [TPAD_050]
TP33  TPAD_050  [TPAD_050]
TP34  TPAD_050  [TPAD_050]
TP39  TPAD_050  [TPAD_050]
TP40  TPAD_050  [TPAD_050]
TP41  TPAD_050  [TPAD_050]
TP42  TPAD_050  [TPAD_050]
U24  74LVC07APW  [TSSOP14]  (sections A,B,C,D,E,F)
U32  74LVC2G07  [SOT363]  (sections A,B)

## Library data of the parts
C9 C46 C52 C55 C66 C71 C74 = CAP_NP: CAP CER 1uF 10V 20% X6S 0402; AGILE_PN: 150-80349; CAD_APPROVED: Yes; FPLIST: CC0402_25,CC0402_HD,0402_CC; HEIGHT: 0.33 MM; MFG_NAME01: TDK; MFG_PN01: CGB2A1X6S1A105M033BC; Package Size: 0402; ROHS: Yes; Temp Range: -55 to +105°C; Tolerance: +/-20%; VOLTAGE: 10V
C42 = CAP_NP: CAP CER 2.2UF 10V 20% X5R 0402; AGILE_PN: 150-79665; CAD_APPROVED: Yes; FPLIST: CC0402_25,CC0402_HD,0402_CC; HEIGHT: 0.55 MM; MFG_NAME01: MURATA; MFG_PN01: GRM155R61A225ME01D; ROHS: Yes; Tolerance: 20%; VOLTAGE: 10V
C47 C48 C67 C77 = CAP_NP: CAP CER 4.7UF 10V 10% X5R 0603; AGILE_PN: 150-77975; CAD_APPROVED: Yes; FPLIST: CC0603_OV,CC0603,0603_CC; HEIGHT: 0.9MM; MFG_NAME01: TAIYO YUDEN; MFG_PN01: LMK107BJ475KA-T; Package Size: 0603; Package Type: tape & reel; ROHS: Yes; Tolerance: 10%; VOLTAGE: 10V
D6 D7 = DIODE_SCH_123: DIODE ARRAY SCH RECT 1A 40V 3HUSON; AGILE_PN: 480-79840; CAD_APPROVED: Yes; HEIGHT: 0.65MM; MFG_NAME01: NEXPERIA; MFG_PN01: PMEG4010CPA,115; REQUESTED_COMPLETION_DATE: Not an expedite request; ROHS: Yes; Temp Range: -55C to +150C; Temp_Range: -55C to +150C
FB1 = BEAD: IND FER BEAD 330OHM@100MHZ 1.7A 0603; AGILE_PN: 180-78156; CAD_APPROVED: Yes; HEIGHT: 0.95MM; MFG_NAME01: TDK; MFG_PN01: MPZ1608S331A; PART_TYPE: FERRITE\BEAD; ROHS: Yes; TOL: 25%; Tolerance: 25%
J5 = USB_MINI_B_SKT: CON 5 USB MICRO_B RA SKT SMT 0.65MM SP 117H AU; AGILE_PN: 211-80405; CAD_APPROVED: Yes; HEIGHT: 2.96MM; MFG_NAME01: WURTH ELEKTRONIK EISOS GMBH & CO. KG (ELECTRONIC & ELECTROMEHANICAL COMP); MFG_PN01: 629105150521; ROHS: Yes; SILK: LINK USB; Temp Range: -40 to +85C
J6 = USB_MINI_B_SKT: CON 5 USB MICRO_B RA SKT SMT 0.65MM SP 117H AU; AGILE_PN: 211-80405; CAD_APPROVED: Yes; HEIGHT: 2.96MM; MFG_NAME01: WURTH ELEKTRONIK EISOS GMBH & CO. KG (ELECTRONIC & ELECTROMEHANICAL COMP); MFG_PN01: 629105150521; ROHS: Yes; SILK: EXT PWR; Temp Range: -40 to +85C
J7 = MICRO_USB_CONN_9PIN: CON 5 USB MICRO-AB RA SKT SMT 0.65MM SP AU; AGILE_PN: 211-78692; CAD_APPROVED: Yes; HEIGHT: 2.8MM; MFG_NAME01: Hirose; MFG_PN01: ZX62D-AB-5P8(30); ROHS: Yes; SILK: RT685 USB
L1 L8 = BEAD: IND FER BEAD 220OHM@100MHZ 2A 0603; AGILE_PN: 180-78695; CAD_APPROVED: Yes; FPLIST: IND_0603,0603_CC; HEIGHT: 0.95MM; MFG_NAME01: LAIRD TECHNOLOGIES; MFG_PN01: MI0603L221R-10; PART_TYPE: FERRITE; ROHS: Yes; Temp Range: -40C to 125C; Temp_Range: -40C to 125C
Q1 = MOSFET_N: TRAN NMOS 60V 360MA AEC-Q101 TO-236AB; AGILE_PN: 480-79842; CAD_APPROVED: Yes; HEIGHT: 1.1MM; MFG_NAME01: NEXPERIA; MFG_PN01: BSS138P,215; ROHS: Yes; Temp Range: -65°C ~ 150°C; Temp_Range: -65°C ~ 150°C; VOLTAGE: 60V
R22 R54 = RES: RES MF 470 OHM 1/16W 5% 0402; AGILE_PN: 470-30315; CAD_APPROVED: Yes; FPLIST: RC0402_25,RC0402_HD,0402_CC; HEIGHT: 0.45mm; MFG_NAME01: SMEC; MFG_PN01: RC73L2Z471JTF; ROHS: Yes; Tolerance: 5%; VOLTAGE: 1/16W
R53 R133 = RES: RES MF 47K  1/16W 1% 0402; AGILE_PN: 470-31023; CAD_APPROVED: Yes; FPLIST: RC0402_25,RC0402_HD,0402_CC; HEIGHT: 0.40 MM; MFG_NAME01: YAGEO AMERICA; MFG_PN01: RC0402FR-0747KL; ROHS: Yes; Temp Range: –55 °C to +155 °C; Temp_Range: –55 °C to +155 °C; Tolerance: 1%
R55 = RES: RES MF 2.2K 1/16W 5% 0402; AGILE_PN: 470-76602; CAD_APPROVED: Yes; FPLIST: RC0402_25,RC0402_HD,0402_CC; HEIGHT: 0.4 MM; MFG_NAME01: YAGEO AMERICA; MFG_PN01: RC0402JR-072K2L; ROHS: Yes; Temp_Range: -55C to +155C; Tolerance: 5%
R3 R60 R124 R128 R131 R148 R308 R310 R372 R383 = RES: RES MF 100K 1/16W 5% 100ppm/C 0402; AGILE_PN: 470-82058; CAD_APPROVED: Yes; FPLIST: RC0402_25,RC0402_HD,0402_CC; HEIGHT: 0.40 MM; MFG_NAME01: YAGEO AMERICA; MFG_PN01: RC0402JR-07100KL; ROHS: Yes; Temp Range: -55C to +155C; Tolerance: 5%; VOLTAGE: 50V
TP12-TP14 TP21-TP26 TP32-TP34 TP38-TP42 = TEST_POINT_L: TEST POINT PAD 50MIL DIA SMT, NO PART TO ORDER; AGILE_PN: 211-76644; CAD_APPROVED: Yes; EN: 666-1-00186; HEIGHT: 0.1MM; KEY Number: 666-1-00186@1; MFG_NAME01: NOTACOMPONENT; MFG_PN01: NOTACOMPONENT; Mfg: NA; Mfg Part No: 666-1-00186; ROHS: Yes
U13 = NX5P3090UK_WLCSP12: IC USB PD TYPE C CURRENT LIMITED PWR SW 2.5-5.5V WLCSP12; AGILE_PN: 312-81574; CAD_APPROVED: Yes; HEIGHT: 0.565 MM; MFG_NAME01: NXP SEMICONDUCTORS; MFG_PN01: NX5P3090UK,012; ROHS: Yes
U21 U22 = PRTR5V0U2X: IC USB ESD PROTECTION 8KV SOT143; AGILE_PN: 315-76725; CAD_APPROVED: Yes; HEIGHT: 1.1MM; MFG_NAME01: NEXPERIA; MFG_PN01: PRTR5V0U2X,215; ROHS: Yes; Temp Range: -40° C to +85° C; Temp_Range: -40° C to +85° C; VOLTAGE: 5.0V
C1 C53 C63 C72 C75 C78 C328 C331 C336 C337 = CAP_NP: CAP CER 0.1UF 25V 20% X5R 0402; AGILE_PN: 150-80403; CAD_APPROVED: Yes; FPLIST: CC0402_25,CC0402_HD,0402_CC; HEIGHT: 0.55MM; MFG_NAME01: WURTH ELEKTRONIK EISOS GMBH & CO. KG (ELECTRONIC & ELECTROMEHANICAL COMP); MFG_PN01: 885012105018; ROHS: Yes; Temp Range: -55°C to +85°C; Temp_Range: -55°C to +125°C; VOLTAGE: 25V
J31 = HDR-2X7: HDR 2X7 TH 100MIL CTR 338H AU 100L; AGILE_PN: 210-81087; CAD_APPROVED: Yes; FPLIST: JUMP2X7-6040,HDR2X7; HEIGHT: 8.59MM; MFG_NAME01: SAMTEC; ROHS: Yes
R300-R307 R377-R380 = RES_3PIN: RES MF ZERO OHM 1/10W -- 0603; AGILE_PN: 470-80866; CAD_APPROVED: Yes; FPLIST: RC0603_OV,RC0603,R603-X2,0603_CC,IND_0603HP_NSP,CC0603_OV_NSP; HEIGHT: 0.6MM; MFG_NAME01: YAGEO AMERICA; MFG_PN01: RC0603FR-070RL; ROHS: Yes; Temp Range: –55 °C to +155 °C; Temp_Range: –55 °C to +155 °C
R407 R408 R413-R416 = RES: RES MF 2.2K 1/16W 5% 0402; AGILE_PN: 470-76602; ASSY_OPT: DNP; CAD_APPROVED: Yes; FPLIST: RC0402_25,RC0402_HD,0402_CC; HEIGHT: 0.4 MM; MFG_NAME01: YAGEO AMERICA; MFG_PN01: RC0402JR-072K2L; ROHS: Yes; Temp_Range: -55C to +155C; Tolerance: 5%
U40 U41 = MIC_SPH0641LM4H-1_5P: MICROPHONE DIGITAL ZERO HEIGHT SISONIC 64DB -0.3-5V SMT; AGILE_PN: 510-78168; CAD_APPROVED: Yes; HEIGHT: 1.08MM; MFG_NAME01: KNOWLES ACOUSTICS; ROHS: Yes; Temp Range: -40C to +100C; VOLTAGE: -0.3-5V
C41 C57 = CAP_NP: CAP CER 22uF 10V 20% X5R 0603; AGILE_PN: 150-79530; CAD_APPROVED: Yes; FPLIST: CC0603_OV,CC0603,0603_CC; HEIGHT: 1MM; MFG_NAME01: TDK; MFG_PN01: C1608X5R1A226M080AC; Package Size: 0603; ROHS: Yes; Tolerance: 20%; VOLTAGE: 10V
C43 C44 C49 C61 C64 C70 C250 C252 = CAP_NP: CAP CER 10uF 16V 20% X5R 0603; AGILE_PN: 150-80336; CAD_APPROVED: Yes; FPLIST: CC0603_OV,CC0603; HEIGHT: 1MM; MFG_NAME01: MURATA; MFG_PN01: GRM188R61C106MA73D; Package Size: 0603; Package Type: SMD; ROHS: Yes; Tolerance: 20%; VOLTAGE: 16V
C45 C54 C65 C73 = CAP_NP: CAP CER 18pF 25V 5% C0G 0402; AGILE_PN: 150-78760; CAD_APPROVED: Yes; FPLIST: CC0402_25,CC0402_HD,0402_CC; HEIGHT: 0.56MM; MFG_NAME01: AVX; MFG_PN01: 04023A180JAT2A; ROHS: Yes; Tolerance: 5%; VOLTAGE: 25V
C76 = CAP_NP: CAP CER 100uF 16V 20% X5R 1210; AGILE_PN: 150-79142; CAD_APPROVED: Yes; FPLIST: CC1210,1210_CC; HEIGHT: 2.8MM; MFG_NAME01: TAIYO YUDEN; MFG_PN01: EMK325ABJ107MM-T; Package Size: 1210; ROHS: Yes; Tolerance: 20%; VOLTAGE: 16V
J11 = TB2: CON 1X2 TB TH 5MM SP 398H SN 138L; AGILE_PN: 210-80469; CAD_APPROVED: Yes; HEIGHT: 10.1MM; MFG_NAME01: WURTH ELEKTRONIK EISOS GMBH & CO. KG (ELECTRONIC & ELECTROMEHANICAL COMP); MFG_PN01: 691102710002; ROHS: Yes
J20 = TB2: CON 1X2 TB TH 5MM SP 398H SN 138L; AGILE_PN: 210-80469; CAD_APPROVED: Yes; HEIGHT: 10.1MM; MFG_NAME01: WURTH ELEKTRONIK EISOS GMBH & CO. KG (ELECTRONIC & ELECTROMEHANICAL COMP); MFG_PN01: 691102710002; ROHS: Yes; SILK: SPEAKER
J24 = CONN_3P_POWERJACK: CON 3 PWR JACK SKT RA TH 433H AG 138L; AGILE_PN: 210-80321; CAD_APPROVED: Yes; HEIGHT: 11MM; MFG_NAME01: CLIFF ELECTRONIC COMPONENTS; MFG_PN01: FC681465P; ROHS: Yes; SILK: 5V JACK
JP11 = CONN_HDR_3X1: HDR 1X3 TH 100MIL SP 339H AU 100L; AGILE_PN: 210-75726; CAD_APPROVED: Yes; HEIGHT: 8.65MM; MFG_NAME01: SAMTEC; MFG_PN01: TSW-103-07-G-S; Package Size: 7.62 x 2.54 mm; ROHS: Yes; Temp Range: -55°C to +125°C; Temp_Range: -55°C to +125°C; VOLTAGE: 450 - 550 VAC
JS7 = CONN_HDR_2X1: HDR 1X2 TH 100MIL SP 339H AU 98L; AGILE_PN: 210-75439; ASSY_OPT: DNP; CAD_APPROVED: YES; FPLIST: HDR102,SH_HDR102_BOTTOM; HEIGHT: 8.71 MM; MFG_NAME01: SAMTEC; MFG_PN01: TSW-102-07-G-S; ROHS: Yes; Temp Range: -55°C to +125°C; Temp_Range: -55°C to +125°C
L4 L7 = INDUCTOR: IND PWR 1uH@1MHZ 3.1A 20% 0806; AGILE_PN: 180-78820; CAD_APPROVED: Yes; HEIGHT: 1mm; MFG_NAME01: TDK; MFG_PN01: TFM201610ALM-1R0MTAA; Package Size: 0806; ROHS: Yes; Temp Range: -40° C to +125° C; Temp_Range: -40° C to +125° C; Tolerance: 20%
L5 L6 L9 L10 = INDUCTOR_FERRITE: IND FER 120 OHM@100MHZ 2A 25% 0402; AGILE_PN: 180-78315; CAD_APPROVED: Yes; FPLIST: IND_0402,0402_CC; HEIGHT: 0.55MM; MFG_NAME01: MURATA; MFG_PN01: BLM15PX121SN1; PART_TYPE: FERRITE\BEAD; ROHS: Yes; Tolerance: 25%
R51 R59 R62 R65 = RES: RES MF 4.7K 1/16W 5% 100ppm/C 0402; AGILE_PN: 470-82066; CAD_APPROVED: Yes; FPLIST: RC0402_25,RC0402_HD,0402_CC,RC0402_X2; HEIGHT: 0.41mm; MFG_NAME01: YAGEO AMERICA; MFG_PN01: RC0402JR-074K7L; ROHS: Yes; Temp Range: -55C to +155C; Tolerance: 5%; VOLTAGE: 50V
R52 R57 R63 R64 = RES: RES MF 100 OHM 1/16W 5% 0402; AGILE_PN: 470-82143; ASSY_OPT: DNP; CAD_APPROVED: Yes; FPLIST: RC0402_25,RC0402_HD,RC0402_X2,0402_CC; HEIGHT: 0.45MM; MFG_NAME01: YAGEO AMERICA; MFG_PN01: RC0402JR-07100RL; ROHS: Yes; Temp Range: -55°C to +155°C; Tolerance: 5%
U12 U17 = TFA9894D_48P: IC AMP AUDIO PWR 5.6/6.2W 2.7-5.5V WLCSP48; AGILE_PN: TMP-WF-33886; CAD_APPROVED: Yes; HEIGHT: 0.54MM; MFG_NAME01: NXP SEMICONDUCTORS; PRE_APN: 315-81967; ROHS: Yes; VOLTAGE: 2.7-5.5V
U15 = 2-input_or: IC GATE OR -- 1.65-5.5V SC70; AGILE_PN: 312-79785; CAD_APPROVED: Yes; HEIGHT: 1.1MM; MFG_NAME01: Fairchild; ROHS: Yes
U16 = NC7SZ14: IC INV SGL 1.65-5.5V TSSOP5; AGILE_PN: 315-81077; CAD_APPROVED: Yes; HEIGHT: 1.1MM; MFG_NAME01: NEXPERIA; MFG_PN01: 74LVC1G04GW,125; ROHS: Yes; VOLTAGE: 1.65-5.5V
U34 = NTB0104BQ: IC DUAL XLTR XCVR 4BIT 1.2-3.6/1.65-5.5V DHVQFN14; AGILE_PN: 312-81227; CAD_APPROVED: Yes; HEIGHT: 1MM; MFG_NAME01: NXP SEMICONDUCTORS; MFG_PN01: NTB0104BQ,115; ROHS: Yes; VOLTAGE: 1.2-3.6V/1.65-5.5V
BH1 = MOUNT_HOLE: FASTENER, STANDOFF M2.5-0.45 ROUND FEMALE OD CS L2MMX1MM; AGILE_PN: 280-77165; CAD_APPROVED: Yes; HEIGHT: 2.13MM; MFG_NAME01: SHENZHEN SINHOO SCIENCE TECHNOLOGY DEVELOPMENT CO.,LTD; MFG_PN01: NXP01-001; ROHS: Yes
C89 = CAP_NP: CAP CER 10.0uF 16V 10% X7R 0805; AGILE_PN: 150-80121; CAD_APPROVED: Yes; FPLIST: CC0805_OV,CC0805,0805_CC,cc0603_0805_nsp; HEIGHT: 1.45MM; MFG_NAME01: MURATA; MFG_PN01: GRM21BZ71C106KE15; Package Size: 0805; Package Type: SMT; ROHS: Yes; Temp Range: -55C to +125C; Temp_Range: -55C to +125C; VOLTAGE: 16V
C251 C253 C319 C320 = CAP_NP: CAP CER 0.1uF 16V 10% X7R 0201; AGILE_PN: 150-80124; CAD_APPROVED: Yes; FPLIST: CC0201,CC0201_HD,0201_CC; HEIGHT: 0.33MM; MFG_NAME01: MURATA; MFG_PN01: GRM033Z71C104KE14; Package Size: 0201; ROHS: Yes; Temp Range: -55°C ~ 125°C; Temp_Range: -55°C ~ 125°C; Tolerance: 10%; VOLTAGE: 16V
C321 = CAP_NP: CAP CER 0.01uF 16V 10% X7R 0201; AGILE_PN: 150-80313; ASSY_OPT: DNP; CAD_APPROVED: Yes; FPLIST: CC0201,CC0201_HD,0201_CC; HEIGHT: 0.33MM; MFG_NAME01: MURATA; MFG_PN01: GRM033R71C103KE14D; Package Size: 0201; ROHS: Yes; Temp Range: -55 to 125°C; Temp_Range: -55 to 125°C; Tolerance: 10%; VOLTAGE: 16V
D1 D22 D23 = LED: LED BRIGHT RED CLEAR SGL 2V 20MA SMT 0603; AGILE_PN: 370-76779; CAD_APPROVED: Yes; HEIGHT: 0.80MM; MFG_NAME01: WURTH ELEKTRONIK EISOS GMBH & CO. KG (ELECTRONIC & ELECTROMEHANICAL COMP); MFG_PN01: 150060RS75000; REQUESTED_COMPLETION_DATE: Not an expedite request; ROHS: Yes; VOLTAGE: 2V
D26 = DIODE_TVS: DIODE TVS UNIDIR 3.3VWM 20VC SOD523; AGILE_PN: 480-79814; CAD_APPROVED: Yes; HEIGHT: 0.65MM; MFG_NAME01: NEXPERIA; MFG_PN01: PESD3V3S1UB,115; REQUESTED_COMPLETION_DATE: Not an expedite request; ROHS: Yes
J32 = CONN_SDCARD_PUSH_PULL_9P_SH2: CON 9 SD CARD PUSH-PULL SKT SMT RA 2.5MM SP 120H AU; AGILE_PN: 211-80186; CAD_APPROVED: Yes; HEIGHT: 3.05 MM; MFG_NAME01: WURTH ELEKTRONIK EISOS GMBH & CO. KG (ELECTRONIC & ELECTROMEHANICAL COMP); MFG_PN01: 693061010911; ROHS: Yes; SILK: SD CARD; Temp Range: -25°C to +85°C; Temp_Range: -25°C to +85°C
J45 = CON_67_FEMALE_RA: CON 67 M.2 NGFF MINI CARD DOUBLE SIDE RA SMT 0.5MM SP 165H AU; AGILE_PN: 211-80173; ASSY_OPT: DNP; CAD_APPROVED: Yes; HEIGHT: 4.2 MM; MFG_NAME01: TE CONNECTIVITY LTD; MFG_PN01: 2199230-4; ROHS: Yes; SILK: M.2 CONN; Temp Range: -40C to 80C; Temp_Range: -40C to 80C
Q15 Q16 = 2SK3018: TRANS MOSFET N-CH 30V .1A SOT-323; AGILE_PN: 480-75317; CAD_APPROVED: Yes; HEIGHT: 0.9MM; MFG_NAME01: ROHM; MFG_PN01: 2SK3018T106; ROHS: Yes
R200 = RES: RES MF 22 OHM 1/16W 5% 0402; AGILE_PN: 470-75605; CAD_APPROVED: Yes; FPLIST: RC0402_25,RC0402_HD,0402_CC; HEIGHT: 0.4MM; MFG_NAME01: BOURNS; MFG_PN01: CR0402-JW-220GLF; ROHS: Yes; Tolerance: 5%
R201-R208 R210-R213 R215-R218 = RES: RES MF ZERO OHM 1/16W -- AEC-Q200 0402; AGILE_PN: 470-81849; CAD_APPROVED: Yes; FPLIST: RC0402_25,RC0402_HD,0402_CC; HEIGHT: 0.45 MM; MFG_NAME01: STACKPOLE ELECTRONICS; MFG_PN01: RMCF0402ZT0R00; ROHS: Yes
R104 R105 R209 R231 = RES: RES MF 10K 1/16W 5% 0402; AGILE_PN: 470-75557; CAD_APPROVED: Yes; FPLIST: RC0402_25,RC0402_HD,0402_CC; HEIGHT: 0.4 MM; MFG_NAME01: VISHAY INTERTECHNOLOGY; MFG_PN01: CRCW040210K0JNED; ROHS: Yes; Tolerance: 5%
R221 R222 R373 R423 = RES: RES MF ZERO OHM 1/16W -- AEC-Q200 0402; AGILE_PN: 470-81849; ASSY_OPT: DNP; CAD_APPROVED: Yes; FPLIST: RC0402_25,RC0402_HD,0402_CC; HEIGHT: 0.45 MM; MFG_NAME01: STACKPOLE ELECTRONICS; MFG_PN01: RMCF0402ZT0R00; ROHS: Yes
R224 R225 = RES: RES 510 OHMS 1/16W 5% RC0402 ROHS; AGILE_PN: 470-76237; CAD_APPROVED: Yes; FPLIST: RC0402_25,RC0402_HD,0402_CC; HEIGHT: 0.4 MM; MFG_NAME01: YAGEO AMERICA; MFG_PN01: RC0402JR-07510RL; ROHS: Yes
R226-R229 = RES: RES MF 4.7K 1/16W 5% 100ppm/C 0402; AGILE_PN: 470-82066; CAD_APPROVED: Yes; FPLIST: RC0402_25,RC0402_HD,0402_CC,RC0402_X2; HEIGHT: 0.41mm; MFG_NAME01: YAGEO AMERICA; MFG_PN01: RC0402JR-074K7L; ROHS: Yes; Temp Range: -55C to +155C; Temp_Range: -55C to +155C; Tolerance: 5%; VOLTAGE: 50V
R309 = RES: RES MF 4.7K 1/16W 5% 100ppm/C 0402; AGILE_PN: 470-82066; ASSY_OPT: DNP; CAD_APPROVED: Yes; FPLIST: RC0402_25,RC0402_HD,0402_CC,RC0402_X2; HEIGHT: 0.41mm; MFG_NAME01: YAGEO AMERICA; MFG_PN01: RC0402JR-074K7L; ROHS: Yes; Temp Range: -55C to +155C; Temp_Range: -55C to +155C; Tolerance: 5%; VOLTAGE: 50V
Y8 = OSC_ASFL: OSC 32.768KHz +/-50ppm HCMOS 15pF 3.3V SMD; AGILE_PN: 230-78164; CAD_APPROVED: Yes; HEIGHT: 1MM; MFG_NAME01: BOMAR CRYSTAL COMPANY; MFG_PN01: B1350-BSBS3T-32.768KHZ; ROHS: Yes; SILK: 32K; Temp Range: -10C to 70C; Temp_Range: -10C to 70C; VOLTAGE: 3.3V
J19 = CONN_HDR_10X2: HDR 2X10 SMT 1.27MM SP 235H AU; AGILE_PN: 211-79169; CAD_APPROVED: Yes; HEIGHT: 5.97MM; MFG_NAME01: SAMTEC; MFG_PN01: FTSH-110-01-F-DV; ROHS: Yes; SILK: RT685 DEBUG TRACE
J38 = MICTOR38P: CON 2X19 PLUG SMT MICTOR 0.64MM SP AU; AGILE_PN: 211-76641; ASSY_OPT: DNP; CAD_APPROVED: Yes; HEIGHT: 6.60MM; MFG_NAME01: TYCO ELECTRONICS; MFG_PN01: 5767111-8; ROHS: Yes; VOLTAGE: 30Vac
Q8 = MOSFET_P: TRAN PMOS 20V 3.5A SOT23; AGILE_PN: 480-79843; CAD_APPROVED: Yes; HEIGHT: 1.1MM; MFG_NAME01: NEXPERIA; MFG_PN01: PMV48XP,215; ROHS: Yes; Temp Range: -65°C ~ 150°C; Temp_Range: -65°C ~ 150°C; VOLTAGE: 20V
R1 R2 R58 R130 = RES: RES MF 100 OHM 1/16W 5% 0402; AGILE_PN: 470-82143; CAD_APPROVED: Yes; FPLIST: RC0402_25,RC0402_HD,RC0402_X2,0402_CC; HEIGHT: 0.45MM; MFG_NAME01: YAGEO AMERICA; MFG_PN01: RC0402JR-07100RL; ROHS: Yes; Temp Range: -55°C to +155°C; Tolerance: 5%
R132 = RES_0603_X2: RES MF ZERO OHM 1/10W -- 0603; AGILE_PN: 470-80866; CAD_APPROVED: Yes; FPLIST: RC0603_OV,RC0603,R603-X2,0603_CC,IND_0603HP_NSP,CC0603_OV_NSP; HEIGHT: 0.6MM; MFG_NAME01: YAGEO AMERICA; MFG_PN01: RC0603FR-070RL; ROHS: Yes; Temp Range: –55 °C to +155 °C; Temp_Range: –55 °C to +155 °C
SH11-SH14 SH17-SH21 = RES_SHORT-2: ZERO OHM CUT TRACE 0603 PADS; NO PART TO ORDER; AGILE_PN: 470-80018; CAD_APPROVED: Yes; FPLIST: SH0603,SH0603_CC,SH0603-X2_PIN1TO2; HEIGHT: 0.1MM; MFG_NAME01: LAYOUT ELEMENT ONLY; MFG_PN01: LAYOUT ELEMENT ONLY; ROHS: Yes
SW3 = SW_PB_4P: SW SPST MOM PB NO 50MA 32V SMT; AGILE_PN: 510-78172; CAD_APPROVED: Yes; HEIGHT: 1.9 MM; MFG_NAME01: C&K COMPONENTS; ROHS: Yes; SILK: RESET BUTTON; Temp Range: -40° C to +85° C; Temp_Range: -40° C to +85° C; VOLTAGE: 32V
U24 = 74LVC07APW: IC BUF HEX 1.65-5.5V TSSOP14; AGILE_PN: 312-75315; HEIGHT: 1.1mm; MFG_NAME01: PHILIPS SEMICONDUCTOR; ROHS: No; VOLTAGE: 1.65-5.5V
U32 = 74LVC2G07: IC BUF OPEN DRAIN OP 1.65V-5.5V SOT363; AGILE_PN: 312-75317; HEIGHT: 1.8mm; MFG_NAME01: NEXPERIA; MFG_PN01: 74LVC2G07GW; ROHS: No; VOLTAGE: 3.3/5V

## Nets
+5V: D6.3(C) D7.3(C) TP13.1(TP) ; also on sheet 7 14
+5V_EXT: C67.1 C77.1 C78.1 J6.1(VBUS) JP11.1 L8.1 U13.B1(VINT1) U13.B2(VINT2) U13.C1(VINT3)
+5V_LINK: D7.2(A2) L1.2 R22.2 ; also on sheet 7
GND: BH1.1 C1.2 C9.2 C41.2 C42.2 C43.2 C44.2 C45.2 C46.2 C47.2 C48.2 C49.2 C52.2 C53.2 C54.2 C55.2 C57.2 C61.2 C63.2 C64.2 C65.2 C66.2 C67.2 C70.2 C71.2 C72.2 C73.2 C74.2 C75.2 C76.2 C77.2 C78.2 C89.2 C250.2 C251.2 C252.2 C253.2 C319.2 C320.2 C321.2 C328.2 C331.2 C336.2 C337.2 D26.A J5.5(GND1) J5.S1(SHLD1) J5.S2(SHLD2) J5.S3(SHLD3) J5.S4(SHLD4) J6.5(GND1) J6.S1(SHLD1) J6.S2(SHLD2) J6.S3(SHLD3) J6.S4(SHLD4) J7.5(GND) J7.6(SHELL1) J7.7(SHELL2) J7.8(SHELL3) J7.9(SHELL4) J19.3 J19.5 J19.15 J19.17 J19.19 J24.2 J24.3 J31.11 J31.12 J32.3(VSS1) J32.6(VSS2) J32.G1(GND1) J32.G2(GND2) J38.5 J38.S1 J38.S2 J38.S3 J38.S4 J38.S5 J45.1(GND1) J45.7(GND2) J45.18(GND3) J45.33(GND5) J45.39(GND4) J45.45(GND6) J45.51(GND7) J45.57(GND8) J45.63(GND9) J45.69(GND10) J45.75(GND11) Q1.2(SOURCE) Q8.3(DRAIN) R53.1 R55.2 R104.2 R231.2 R377.3 R378.1 SW3.3 SW3.4 U12.A4(GNDD) U12.B4(GNDD) U12.B5(GNDD) U12.C2(GNDD) U12.C5(GNDD) U12.D2(GNDD) U12.D3(ADS2/TMS) U12.D4(ADS1/TDI) U12.D5(TRSTN) U12.E2(GNDD) U12.E3(GNDD) U12.E4(TEST2) U12.E5(TEST1) U12.F1(GNDB) U12.F2(GNDB) U12.F3(GNDB) U12.F4(GNDP) U12.F5(GNDD) U12.F6(GNDD) U12.G4(GNDP) U13.B3(GND1) U13.C3(GND2) U13.D3(GND3) U15.3(GND) U16.3(GND) U17.A4(GNDD) U17.B4(GNDD) U17.B5(GNDD) U17.C2(GNDD) U17.C5(GNDD) U17.D2(GNDD) U17.D3(ADS2/TMS) U17.D5(TRSTN) U17.E2(GNDD) U17.E3(GNDD) U17.E4(TEST2) U17.E5(TEST1) U17.F1(GNDB) U17.F2(GNDB) U17.F3(GNDB) U17.F4(GNDP) U17.F5(GNDD) U17.F6(GNDD) U17.G4(GNDP) U21.1(GND) U22.1(GND) U24.7(GND) U32.2(GND) U34.7(GND1) U34.15(GND2) U40.3(GND) U41.3(GND) Y8.2(GND) ; also on sheet 7 8 9 10 11 12 13 14
P1V8_CODEC: C336.1 C337.1 J31.1 J31.2 R377.1 R378.3 U40.5(VDD) U41.5(VDD) ; also on sheet 13
P5V_TRG_JTAG: J19.11 J19.13 TP12.1(TP)
VBST/VDDP_1: C43.1 C44.1 C49.1 C53.1 U12.G5(VDDP) U12.H1(VBST) U12.H2(VBST) U12.H3(VBST) U12.H5(VDDP) U12.H6(VDDP)
VBST/VDDP_2: C61.1 C64.1 C70.1 C72.1 U17.G5(VDDP) U17.H1(VBST) U17.H2(VBST) U17.H3(VBST) U17.H5(VDDP) U17.H6(VDDP)
VBUS0_TARGET: R54.2 R55.1 ; also on sheet 7
VDD_AMP: C41.1 C55.1 C57.1 C74.1 JP11.2 L4.1 L7.1 U12.C6(VBAT) U17.C6(VBAT)
VDD_JACK: C75.1 C76.1 J24.1 JP11.3
VDD_LDO_3V3: R60.2 ; also on sheet 7 10 14
VDD_RST: R132.2 U24.14(3V3) U32.5(3V3)
VDD_TARGET: R1.1 ; also on sheet 7 10
VDDE_A: C52.1 C63.1 C71.1 C328.1 JS7.1 U12.A3(VDDE) U12.B3(VDDE) U12.C3(VDDE) U12.C4(VDDE) U15.5(VCC) U16.5(VCC) U17.A3(VDDE) U17.B3(VDDE) U17.C3(VDDE) U17.C4(VDDE) U17.D4(ADS1/TDI) U34.14(VCCB)
VDDIO1: JS7.2 R58.1 R105.1 R130.1 R133.1 R383.1 R413.1 R414.1 ; also on sheet 7 8 10 12 13 14
ALT_INT_AMP: U34.5(A4) ; also on sheet 13
BT_REG_ON_3V3: C319.1 J45.54(~{W_DISABLE2}) Q16.3(DRAIN) R227.2
CARD_WR_PRT: J32.11(WP) R307.1 R308.2
FC1_CTS_SDA_SSEL0: J31.14 R408.2 ; also on sheet 8 14
FC5_CTS: J45.34(UART_CTS) R212.2
FC5_RTS: J45.36(UART_RTS) R213.2
FC5_RXD: J45.22(UART_RXD) R210.2
FC5_TXD: J45.32(UART_TXD) R211.2
I2S_ALT_INT: U15.4(O) U34.10(B4)
I2S_BCLK_AMP: U12.B1(BCK) U12.B2(MCLK/TCK) U17.B1(BCK) U17.B2(MCLK/TCK) U34.12(B2)
I2S_BCLK_CODEC: R215.2 ; also on sheet 13
I2S_DAI_AMP: U12.D1(DATAI) U17.D1(DATAI) U34.11(B3)
I2S_DAI_CODEC: R217.2 ; also on sheet 13
I2S_DAO_AMP: U12.C1(DATAO) U17.C1(DATAO) ; also on sheet 13
I2S_DAO_CODEC: R218.2 ; also on sheet 13
I2S_WS_AMP: U12.A1(FS) U17.A1(FS) U34.13(B1)
I2S_WS_CODEC: R216.2 ; also on sheet 13
IF_RST: J19.10 R148.2 SH11.1 U24.9(I) ; also on sheet 12
IF_TCK_SWCLK: J19.4 R104.1 SH13.1 ; also on sheet 12
IF_TDO_SWO: J19.6 SH12.1 ; also on sheet 12
INB_1: L4.2 U12.G1(INB) U12.G2(INB) U12.G3(INB)
INB_2: L7.2 U17.G1(INB) U17.G2(INB) U17.G3(INB)
INT1_AMP: U12.A5(INT/TDO) U15.1(I1)
INT2_AMP: U15.2(I2) U17.A5(INT/TDO)
JTAG_VREF: J19.1 J38.12 J38.14 R58.2 R130.2
LDO1_OUT: R3.1 R124.1 R132.1 R148.1 ; also on sheet 7 8 14
LDO2_OUT: R308.1 R309.1 R310.1 ; also on sheet 7 8
M2_32K_3V3: J45.50(SUSCLK) R200.2 R423.2
M2_SD_CDM: R202.1 R303.3
M2_SD_CLK: R201.1 R302.3
M2_SD_DAT0: R203.1 R301.3
M2_SD_DAT1: R204.1 R300.3
M2_SD_DAT2: R205.1 R305.3
M2_SD_DAT3: R206.1 R304.3
M2_SD_RST_B: R208.1 R306.3
M2_SD_WK_B: R207.1 R307.3
M2_USB_DN: J45.5(USB_D-) R222.1
M2_USB_DP: J45.3(USB_D+) R221.1
nRESET_OSPI: R128.2 R373.1 TP34.1(TP) U24.10(O) U24.12(O) ; also on sheet 9
nRESET_OSPI_AP: R372.2 R373.2 TP40.1(TP) U32.6(2Y) ; also on sheet 9
nRESET_PB: C1.1 R2.1 R3.2 U24.1(I)
nRESET_POR: U24.5(I) ; also on sheet 14
nRESET_TRGT: Q8.1(GATE) R124.2 TP32.1(TP) TP39.1(TP) U16.2(A) U24.2(O) U24.4(O) U24.6(O) U24.8(O) U24.11(I) U32.1(2A) ; also on sheet 7 10 12 14
OUTN_1: C54.1 J11.2(B) L6.2 R57.2 R59.2
OUTN_2: C73.1 J20.2(B) L10.2 R64.2 R65.2
OUTP_1: C45.1 J11.1(A) L5.2 R51.2 R52.2
OUTP_2: C65.1 J20.1(A) L9.2 R62.2 R63.2
P0_3: J45.58(I2C_DATA) R415.2 ; also on sheet 8 14
P0_4: J45.60(I2C_CLK) R416.2 ; also on sheet 8 14
P0_7_I2S_CLK: U34.3(A2) ; also on sheet 8 13
P0_8_I2S_WS: U34.2(A1) ; also on sheet 8 13
P0_9_I2S_DAI: U34.4(A3) ; also on sheet 13
P0_11: J31.13 R407.2 ; also on sheet 8 14
P0_12: Q15.1(SOURCE) R229.2 ; also on sheet 8 14
P0_13: Q16.1(SOURCE) R228.2 ; also on sheet 8 14
P0_21: J19.12 SH17.2 ; also on sheet 8
P0_22: J19.14 SH21.2 ; also on sheet 8
P0_23_I2S_DATA_TX: J19.16 SH20.2 ; also on sheet 8 13
P0_24: J19.18 SH19.2 ; also on sheet 8
P0_25: J19.20 SH18.2 ; also on sheet 8
P1_4_SPI_MISO: R211.1 ; also on sheet 8 14
P1_5_SPI_MOSI: R210.1 ; also on sheet 8 10 14
P1_6_SPI_SS0: R212.1 ; also on sheet 8 14
P1_7: R213.1 TP41.1(TP) U32.3(2A) ; also on sheet 8 14
P1_7_RST: TP42.1(TP) U32.4(2Y) ; also on sheet 10
P1_8: R209.1 R231.1 ; also on sheet 8 14
P1_30_SD0_CLK: R302.2 ; also on sheet 8
P1_31_SD0_CMD: R303.2 ; also on sheet 8
P2_0_SD0_D0: R301.2 ; also on sheet 8
P2_1_SD0_D1: R300.2 ; also on sheet 8
P2_2_SD0_D2: R305.2 ; also on sheet 8
P2_3_SD0_D3: R304.2 ; also on sheet 8
P2_4_SD0_WR_PRT: R307.2 TP21.1(TP) ; also on sheet 8
P2_5_SD0_D4: TP24.1(TP) ; also on sheet 8
P2_6_SD0_D5: TP25.1(TP) ; also on sheet 8
P2_7_SD0_D6: TP26.1(TP) ; also on sheet 8
P2_8_SD0_D7: TP14.1(TP) ; also on sheet 8
P2_9_SD0_CD: J32.10(CD_SW) R310.2 TP22.1(TP) ; also on sheet 8
P2_10_SD0_RST_N: R306.2 ; also on sheet 8
P2_11_SD0_VOLT: TP23.1(TP) ; also on sheet 8 14
P2_12: R131.2 TP33.1(TP) U24.13(I) ; also on sheet 8 14
P2_16_PDM_CLK01: R379.2 ; also on sheet 8
P2_17_PDM_CLK23_A: J31.5 ; also on sheet 9
P2_18_PDM_CLK45_A: J31.7 ; also on sheet 9
P2_19_PDM_CLK67_A: J31.9 ; also on sheet 9
P2_20_PDM_DATA01: R380.2 ; also on sheet 8
P2_21_PDM_DATA23_A: J31.6 ; also on sheet 9
P2_22_PDM_DATA45_A: J31.8 ; also on sheet 9
P2_23_PDM_DATA67_A: J31.10 ; also on sheet 9
P2_26_SWDIO: J19.2 R105.2 SH14.1 ; also on sheet 8 12
P2_27_USB1_OVERCURRENTN: R133.2 U13.A2(~{FAULT}) ; also on sheet 8
P2_28_USB1_PWRENA: Q1.1(GATE) R383.2 ; also on sheet 8
P2_29_I3C0_SCL: R413.2 R423.1 U12.A6(SCL) U17.A6(SCL) ; also on sheet 8 10 13
P2_30_I3C0_SDA: R414.2 U12.B6(SDA) U17.B6(SDA) ; also on sheet 8 10 13
PDM_CLK01_Ext: J31.3 R379.3
PDM_CLK01_OnBoard: R379.1 U40.4(CLOCK) U41.4(CLOCK)
PDM_DATA01_Ext: J31.4 R380.3
PDM_DATA01_OnBoard: R380.1 U40.1(DATA) U41.1(DATA)
RESET_AMP: U12.E1(RST) U16.4(Y) U17.E1(RST)
SD_CLK: J32.5(CLK) R302.1
SD_CMD: J32.2(CMD) R303.1 R309.2
SD_DAT0: J32.7(DAT0) R301.1
SD_DAT1: J32.8(DAT1) R300.1
SD_DAT2: J32.9(DAT2) R305.1
SD_DAT3: J32.1(CD/DAT3) R304.1
SD_RST_N: R306.1 ; also on sheet 7
SEL_ON_DMIC_1: R377.2 U40.2(SELECT)
SEL_ON_DMIC_2: R378.2 U41.2(SELECT)
SW2_OUT: C46.1 C66.1 C331.1 Q15.2(GATE) Q16.2(GATE) R128.1 R131.1 R132.3 R228.1 R229.1 R372.1 R407.1 R408.1 R415.1 R416.1 U12.A2(VDDD) U17.A2(VDDD) U34.1(VCCA) U34.8(OE) ; also on sheet 7 8 9 10 11 13 14
SYSRST_B: U24.3(I) ; also on sheet 7
USB0_DM_TRGT: J7.2(D-) R222.2 U22.3(I/O2) ; also on sheet 7
USB0_DP_TRGT: J7.3(D+) R221.2 U22.2(I/O1) ; also on sheet 7
USB_DM_LINK: J5.2(D-) U21.3(I/O2) ; also on sheet 12
USB_DP_LINK: J5.3(D+) U21.2(I/O1) ; also on sheet 12
USB_HS_HOST_VBUS: C42.1 C47.1 C48.1 FB1.2 J7.1(VBUS) U13.C2(VBUS1) U13.D1(VBUS2) U13.D2(VBUS3) U22.4(VCC)
USB_HS_VBUS_TRGT: D6.2(A2) FB1.1 R54.1
USB_ID_LINK: J5.4(ID) ; also on sheet 12
USB_VBUS_LINK: R22.1 ; also on sheet 12
USDHC_SPWR: C89.1 C250.1 C251.1 C252.1 C253.1 C321.1 D26.C J32.4(VDD) J45.2(3V3_1) J45.4(3V3_2) J45.72(3V3_3) J45.74(3V3_4) R224.2 R225.2 R226.1 R227.1 Y8.4(VDD) ; also on sheet 7
VSN_1: R59.1 U12.D6(VSN/TEST4)
VSN_2: R65.1 U17.D6(VSN/TEST4)
VSP_1: R51.1 U12.E6(VSP/TEST3)
VSP_2: R62.1 U17.E6(VSP/TEST3)
WL_REG_ON_3V3: C320.1 J45.56(~{W_DISABLE1}) Q15.3(DRAIN) R226.2
N17855943: L5.1 R52.1 U12.H4(OUTP)
N17855945: L6.1 R57.1 U12.G6(OUTN)
N17886052: L9.1 R63.1 U17.H4(OUTP)
N17886097: L10.1 R64.1 U17.G6(OUTN)
N19506203: R2.2 SW3.1 SW3.2
N19508206: D1.A(ANODE) R1.2
N19508231: D1.C(CATHODE) Q8.2(SOURCE)
N19515068: D7.1(A1) L8.2
N19515078: C9.1 J5.1(VBUS) L1.1 U21.4(VCC)
N19515258: J7.4(ID) TP38.1(TP)
N19519270: R53.2 U13.A3(ILIM)
N19519289: Q1.3(DRAIN) R60.1 U13.A1(EN)
N19798378: J38.6 SH17.1
N19798386: J38.38 SH21.1
N19798394: J38.28 SH20.1
N19798402: J38.26 SH19.1
N19798410: J38.24 SH18.1
N19799787: J38.9 SH11.2
N19799813: J38.11 SH12.2
N19799835: J38.15 SH13.2
N19799857: J38.17 SH14.2
N19896770: J45.9(SDIO_CLK) R201.2
N19896842: J45.11(SDIO_CMD) R202.2
N19896868: J45.13(SDIO_DATA0) R203.2
N19896897: J45.15(SDIO_DATA1) R204.2
N19896926: J45.17(SDIO_DATA2) R205.2
N19896944: J45.19(SDIO_DATA3) R206.2
N19896964: J45.21(~{SDIO_WAKE}) R207.2
N19896972: J45.23(~{SDIO_RST}) R208.2
N19896981: D23.C(CATHODE) J45.6(~{LED1})
N19897044: D22.C(CATHODE) J45.16(~{LED2})
N19897050: D23.A(ANODE) R225.1
N19897088: J45.20(~{UART_WAKE}) R209.2
N19897150: D22.A(ANODE) R224.1
N19897259: J45.8(I2S_SCK) R215.1
N19897289: J45.10(I2S_WS) R216.1
N19897307: J45.12(I2S_SD_IN) R217.1
N19897327: J45.14(I2S_SD_OUT) R218.1
N19898667: R200.1 Y8.3(Output)

Not connected (* = marked no-connect by the designer): D6 1(A1)*; J6 2(D-)* 3(D+)* 4(ID)*; J19 7* 8* 9*; J38 1* 2* 3* 4* 7* 8* 10* 13* 16* 18* 19 20* 21 22* 23* 25* 27* 29* 30* 31* 32* 33* 34* 35* 36* 37*; J45 35(PET_P0)* 37(PET_N0)* 38(VEN_DEF1)* 40(VEN_DEF2)* 41(PER_P0)* 42(VEN_DEF3)* 43(PER_N0)* 44(COEX3)* 46(COEX2)* 47(REFCLK_P0)* 48(COEX1)* 49(REFCLK_N0)* 52(~{PERST0})* 53(~{CLKREQ0})* 55(~{PEWAKE0})* 59(PET_P1)* 61(PET_N1)* 62(~{ALERT})* 64(RESERVED)* 65(PER_P1)* 66(~{PERST1})* 67(PER_N1)* 68(~{CLKREQ1})* 70(~{PEWAKE1})* 71(REFCLK_P1)* 73(REFCLK_N1)*; U16 1(NC)*; U34 6(NC1)* 9(NC2)*; Y8 1(Tri-State)*

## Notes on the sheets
sheet 1
- External DMIC
- I2C_SCL
- I2C_SDA
- On Board DMIC
- SEL = High
- SEL = Low
- Place U40 & U41 at least 1.5" apart each other
sheet 2
- USB HOST
  POWER SWITCH
- TARGET USB
- TARGET Hi-SPD
  USB DEVICE / HOST
  MICRO AB
- Current limit ~500mA
- EXTERNAL PWR
- External +5V
  Power only
  Micro-B
- LINK USB
- Link
  USB Device
  Micro-B
sheet 3
- VDDIO2
- 3.3V logic
- 3.3V logic output
- 3.3V logic input<<
- 3.3V logic input
- 3.3V logic input<<
- 3.3V logic
- WK_B
- bt wakes up host
- 3.3V logic output
- 3.3V logic
- 3.3V logic
- RED LED
- FC5_RXD
- output<<
- input<<
- RED LED
- FC5_TXD
- input>>
- FC5_CTS
- output<<
- FC5_RTS
- input>>
- output>>
- 1.8V logic
- BT AUDIO
- CLKOUT_VDDIO1
- VDDIO1
- input<<
- I2C_SDA
- I2C_SCL
- 1.8V logic
- RT685
- USB I/F
- D+
- D-
- M2 I/F
- close RT685
- M.2 mini Card
- Vgs(th) = 0.8 min, 1.5V max
- for start up timing
- Stand-off for M.2
- SD Card
- Close to SD Card
sheet 4
- RESET
- RESET PB
- RED LED
- RESET LED
- Debug Trace Connector
- Mictor 38 - Trace Adapter
- TRACE_CLKOUT
- SWO
- SWDCLK
- SWDIO
- SWDIO
- JTAG_PWR
- SWDCLK
- SWO
- TRACE_D2
- TRACE_D3
- TRACE_D1
- TRACE_CLKOUT
- TRACE_D0
- TRACE_D1
- TRACE_D2
- TRACE_D3
- TRACE_D0
- DEBUG CONNECTOR
- 50mil pitch header
sheet 5
- EXTERNAL PWR SUPPLY FOR AMP
- MAX INPUT PWR <5.5V
- C41 (Cvbat) = 22uF
- L4 = 1.0uH TDK TFM201610ALM-1R0MTAA
- Cvbst =  Effective value @10V 4.4uF
- C57 (Cvbat) = 22uF
- L7 = 1.0uH TDK TFM201610ALM-1R0MTAA
- Cvbst =  Effective value @10V 4.4uF
- AUDIO AMPLIFIER
sheet 6
- Table of Content
- Revision History
- Page 1
- TITLE PAGE
- Rev. Code
- Date
- Description
- X1
- 07/12/2018
- Rev X1 Draft
- Page 2
- USB Supply Interface
- Parallel I2C translator  1v8 - 3v3
- X2
- 07/19/2018
- Page 3
- System Power
- Audio Amplifier connections updated,
  adding supply voltage for high current
  application
- Page 4
- RT6xx IO
- A
- 08/16/2018
- Released files
- Page 5
- Memory
- B
- 09/13/2018
- xxxx
- Page 6
- Audio Code
- C
- 11/23/2018
- R133, 47k pull-up added
- 100k pull-up added to nRESET_POR
- Page 7
- DMIC
- IF_TCK_SWCLK & IF_SWDIO isolated
  from debug probe
- P1_12_SPI_MISO drive through a separate
  level translator
- Page 8
- Audio Amp - class-D
- Page 9
- Pmod / UART/Flexcomm
- BATTERY HOLDER BT1 changed for a 2x1
  header (S2B-PH-KL)
- U6 replaced for  FXOS8700CQ
- Page 10
- Pheriperals
- J24 replaced for a 6.3mm OD, 2.1/2.5mm ID
- P0_10 now connected to User switch2
- Page 11
- SD & M2 mini card
- P0_27 now connected to J27 pin4 (D3)
- Jumper added to MCU, can be selected
  SW2_OUT or LDO2_OUT domains
- Page 12
- System Reset / Debug Trace
- Update RST control for RT6xx to reset OSPI
- Page 13
- Debug UART
- D
- 07/01/2019
- JP21, R146 & R147 added
- Page 14
- Link2 Debug
- X-MIMXRT685-EVK
- D1
- 09/17/2019
- I2S CODEC/AMP TX/RX signals swapped
- TP38 added for J7 USB ID signal
- Breakouts added for PWR measurement.
- R148 added to IF_RST signal, VDD_RST
  supply by LDO1_OUT
- LDO_ENABLE pullup & pulldown options added
- PCA9420UK changed for QFN
- Octal Flash and pSRAM section updated/added
- SD card and M2 mini card updated
- POWER MANAGEMENT
- J38 Trace connector added
- Accel reset updated
- INPUT
- NET/ PWR NAME
- OUTPUT VOLTAGE
- Audio Codec to work at 1.8V (SW2_OUT)
- TARGET USB
  USB AB
- USB_HS_VBUS_TRGT
  VBUS0_TARGET
- Audio AMP to work at 3.3V (VDDE_A)
- 5V
- CoinCell option removed.
- LINK USB
  MICRO-B USB
- USB_VBUS_LINK
- 5V
- OnBoard DMIC added, I2C availavle at J31
- EXTERNAL PWR
  MICRO-B USB
- +5V_EXT
  +5V
- J47 added for Flexcomm availablility
- 5V
- +5V
  (JS10)
- 5V_SYS
- 5V
- E
- 10/14/2019
- Released
- SW1_OUT
- 0.5V ~ 1.5V
- GENERAL DESIGN NOTES
- SW2_OUT
- 1.5V ~ 2.1V / 2.7V ~ 3.3V
- uPMIC
  (U20)
- E1
- 12/19/2019
- J45 as DNP
- LDO1_OUT
- 1.7V ~ 1.9V
- 1. Unless Otherwise Specified:
- All resistors are in ohms, 5%, 1/16 Watt
- LDO2_OUT
- 1.5V ~ 2.1V / 2.7V ~ 3.3V
- E2
- 02/04/2020
- Jumper configuration added
- All capacitors are in uF, 20%, 50V
- All voltages are DC
- VDD_MEM
  VDD_RST
  P1V8_CODEC
- SW2_OUT
- 1.8V  (default)
- 2. Critical compenents that require tolerances tighter
  than listed in Note 1are labeled with required tolerance
  on schematic. Non-critical components may be filled
  with tighter tolerance parts for BOM consolidation
  purposes, but may be changed to meet the general
  tolerances of Note 1 if desired.
- LDO2_OUT/SW2_OUT
- VDDIO1
- 1.8V / 3.3V
- VDDIO1
  (JP12)
- VDD_CODEC
  VDDE_A
  VDD_PMOD
- 1.8V / 3.3V
- Jumper Configuration
- LDO2_OUT
- VDD_TARGET
- 3.3V  (default)
- 3. Interrupted lines coded with the same letter or letter
  combinations are electrically connected.
- VDD_TARGET
  (JS11)
- V_LED
  VDD_ACCEL
- 3.3V
- 4. Device type number is for reference only. The
  number varies with the manufacturer.
- LOCATION
- PIN
- NCP692
  (U25)
- JP2,JP11,JP12,
  JP15-JP21,
  JP23-JP30
- VDD_LDO_3V3
- 3.3V
- 5. Special signal usage:
- 1-2
- VDD_LDO_3V3
- DCDC_3V3
- 3.3V
- _B or 'n' Denotes - Active-Low Signal
- JP6,JP7,JP8
- 2-3
- NCP1117
  (U14)
- <> or [] Denotes - Vectored Signals
- +2.5V_LINK
- 2.5V
- JP1,JP3,JP4,
  JP9,JP10,JP13,
  JP14
- NCP692
  (U23)
- USDHC_SPWR
- 3.3V
- 6. Interpret diagram in accordance with American
  National Standards Institute specifications, current
  revision, with the exception of logic block symbology.
- 1-OPEN
- JP11
- VDD_AMP
- +5V_EXT/ EXTERNAL JACK
- SW5
- ON,OFF,ON
